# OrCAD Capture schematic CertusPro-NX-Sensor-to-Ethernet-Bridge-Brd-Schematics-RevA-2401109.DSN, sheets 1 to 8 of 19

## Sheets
1 Title Page: title: CP-NX Sensor To Ethernet Bridge Board; rev: 1.0; note: 305-PD-24-0244
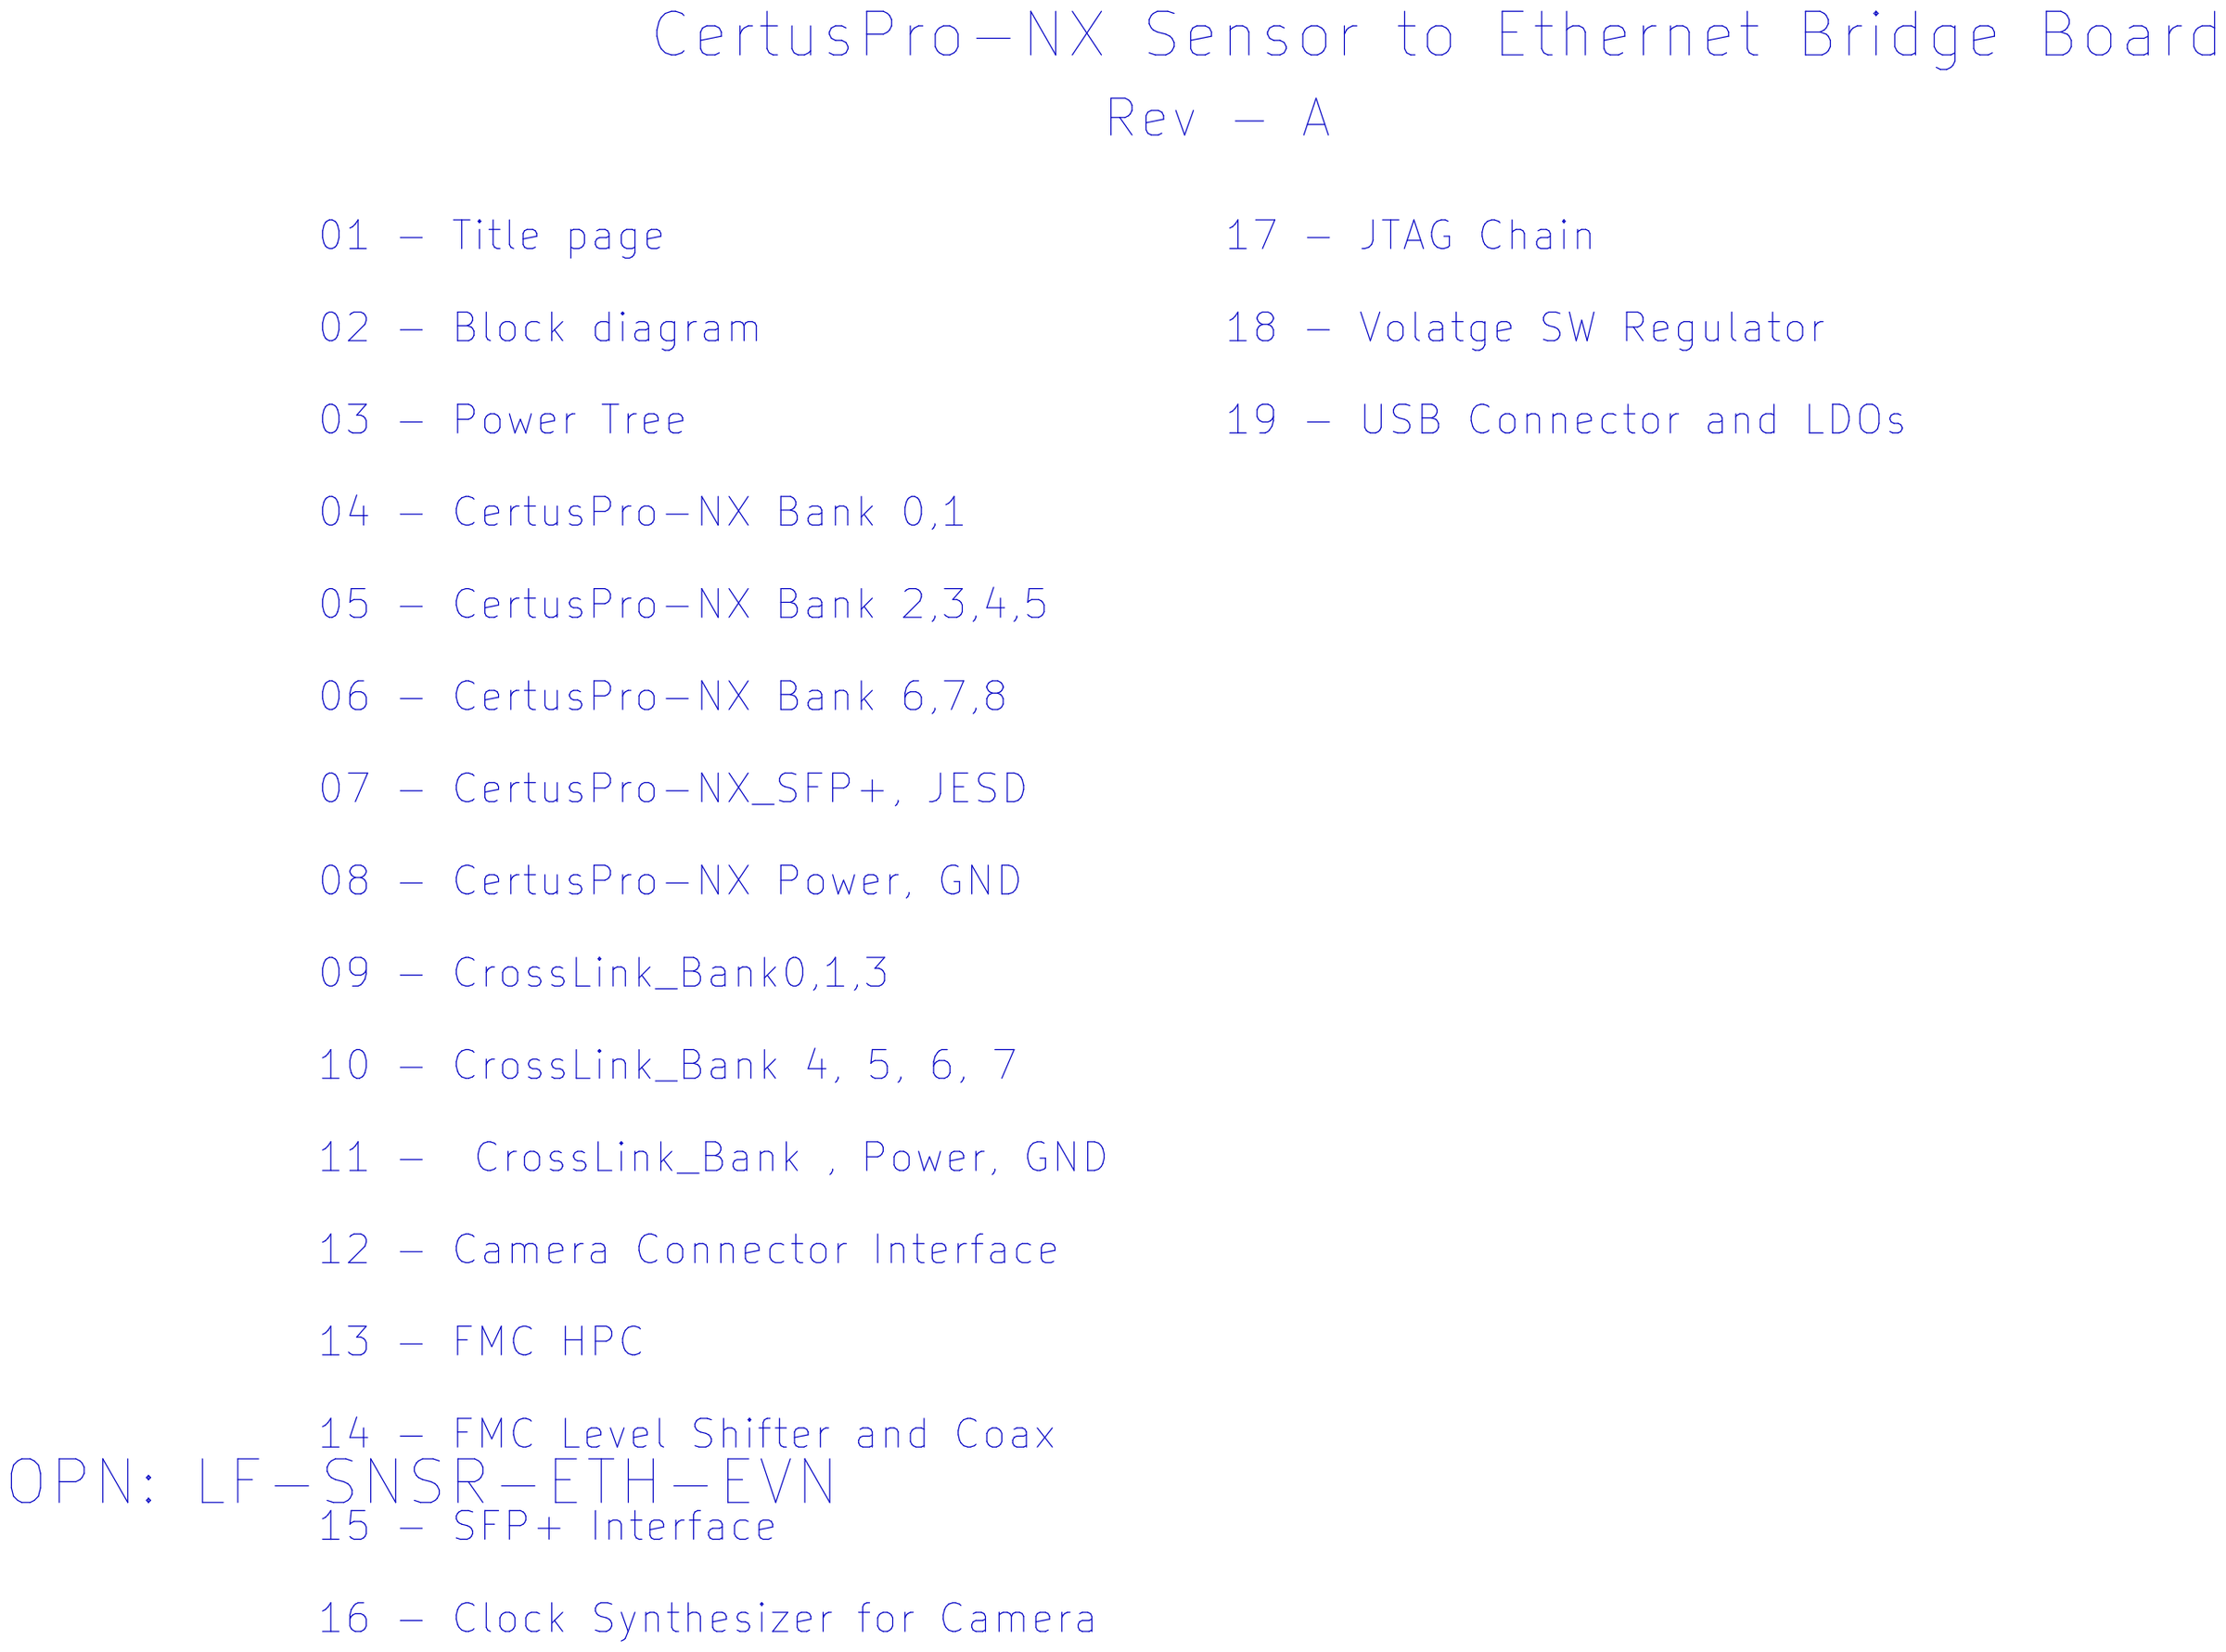
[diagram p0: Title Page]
2 Block Diagram
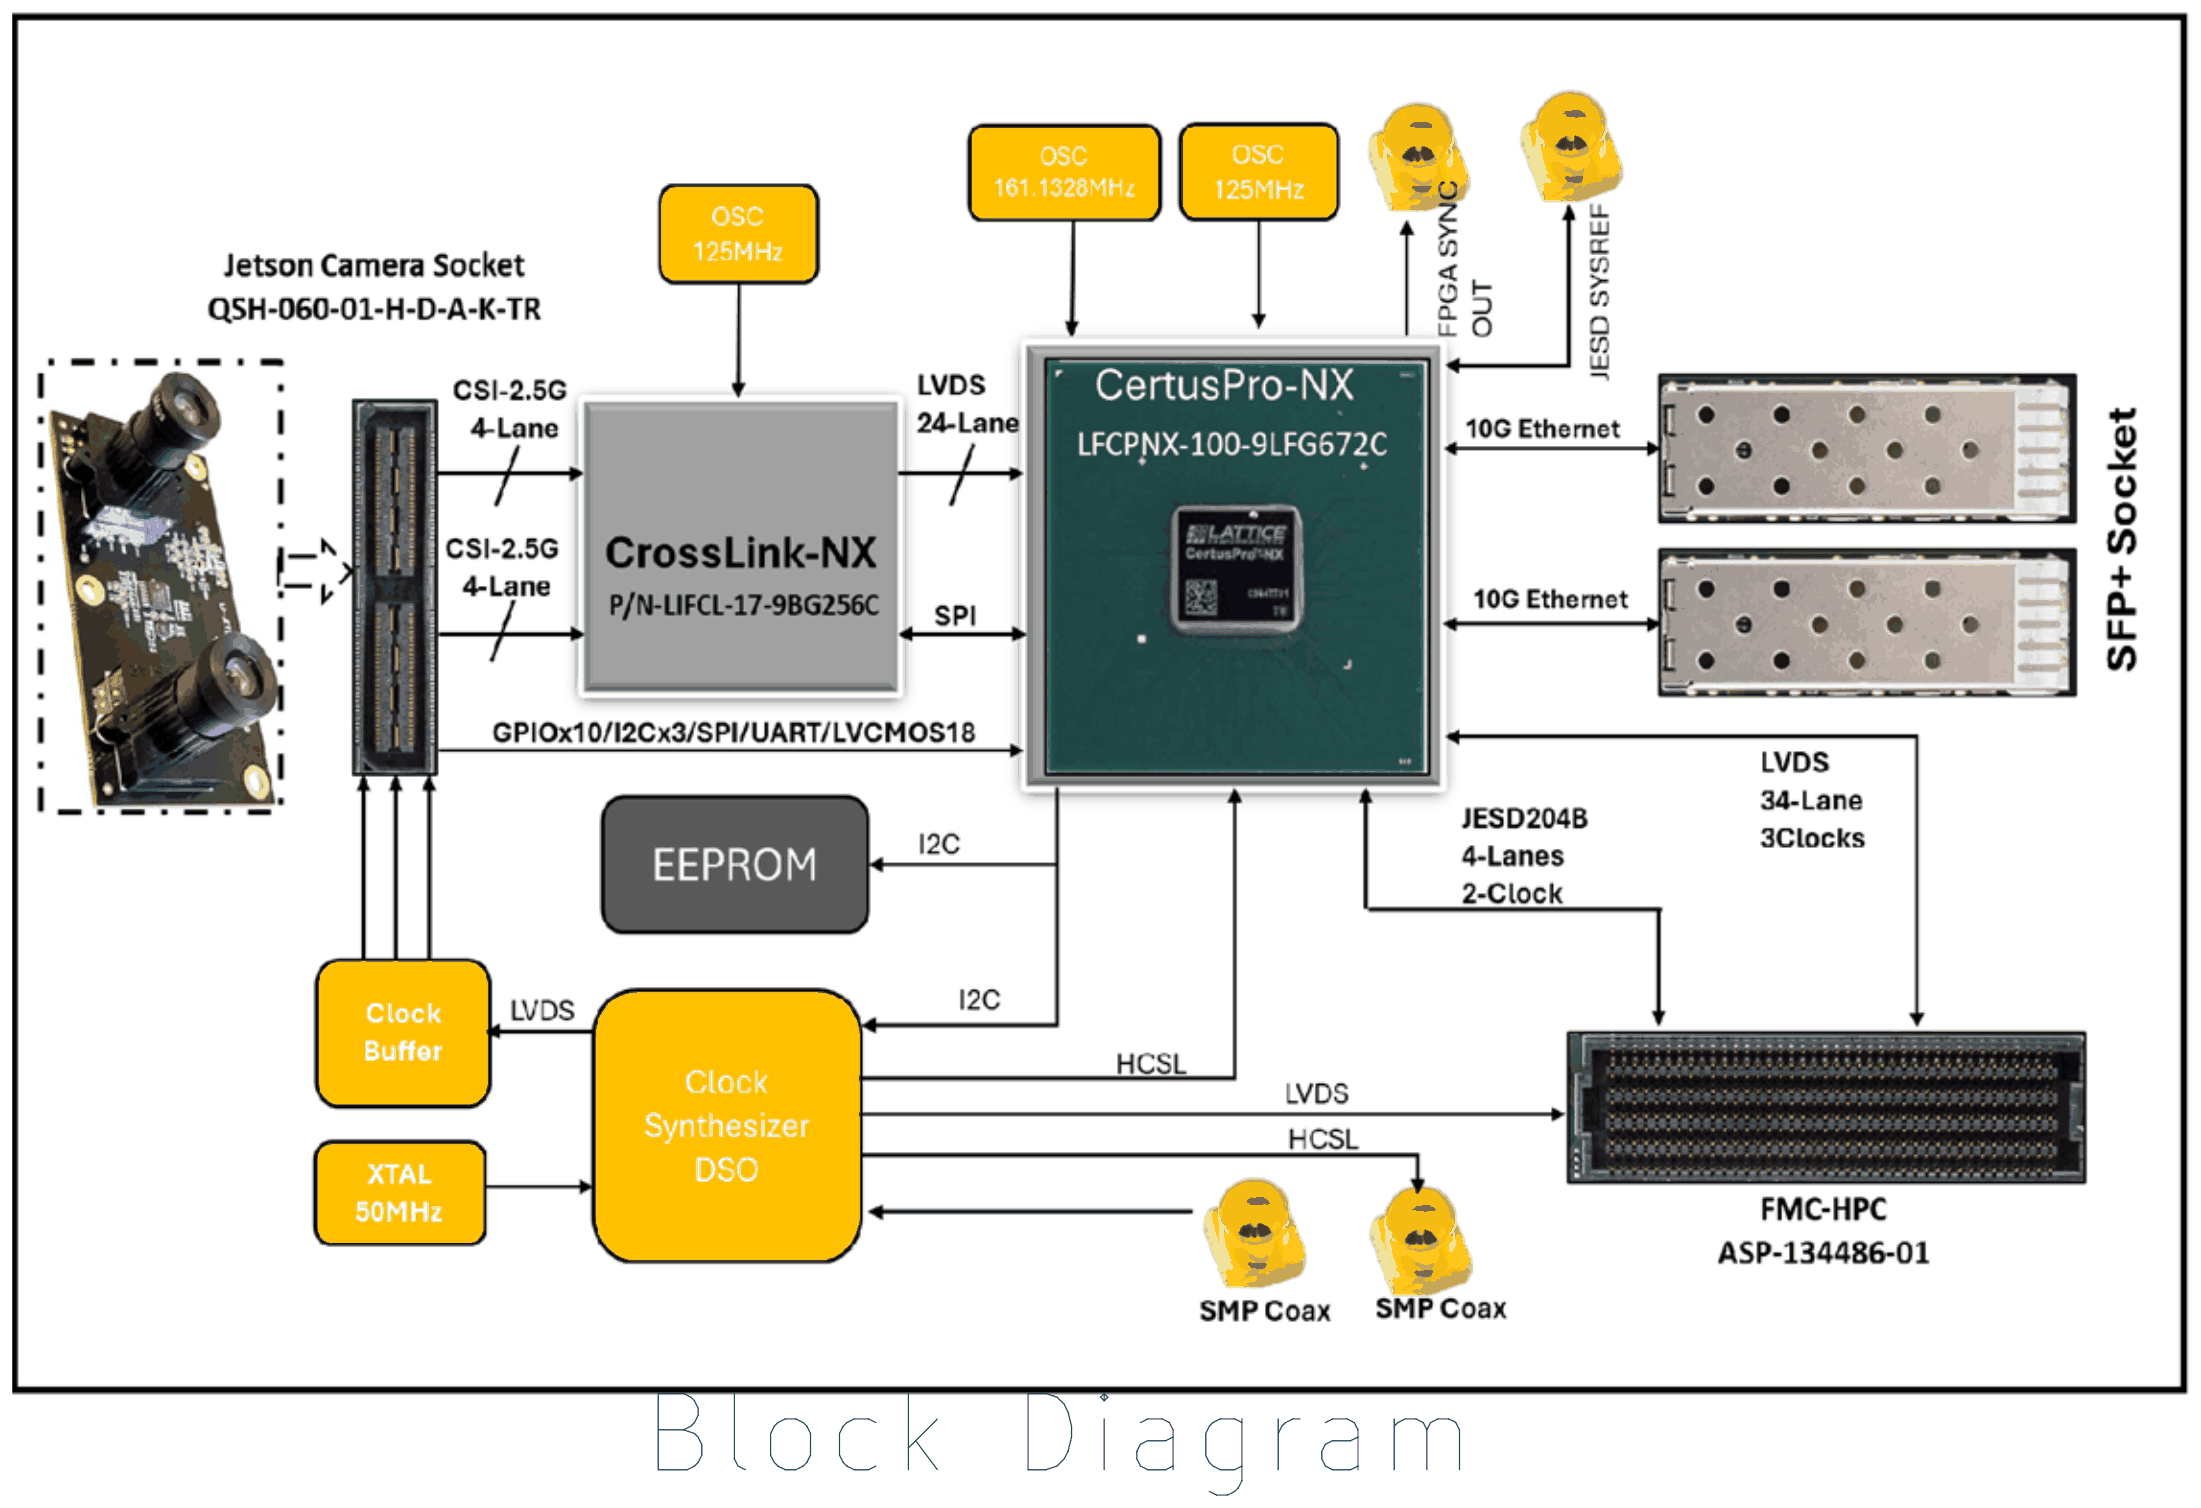
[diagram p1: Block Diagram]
3 Power_Tree
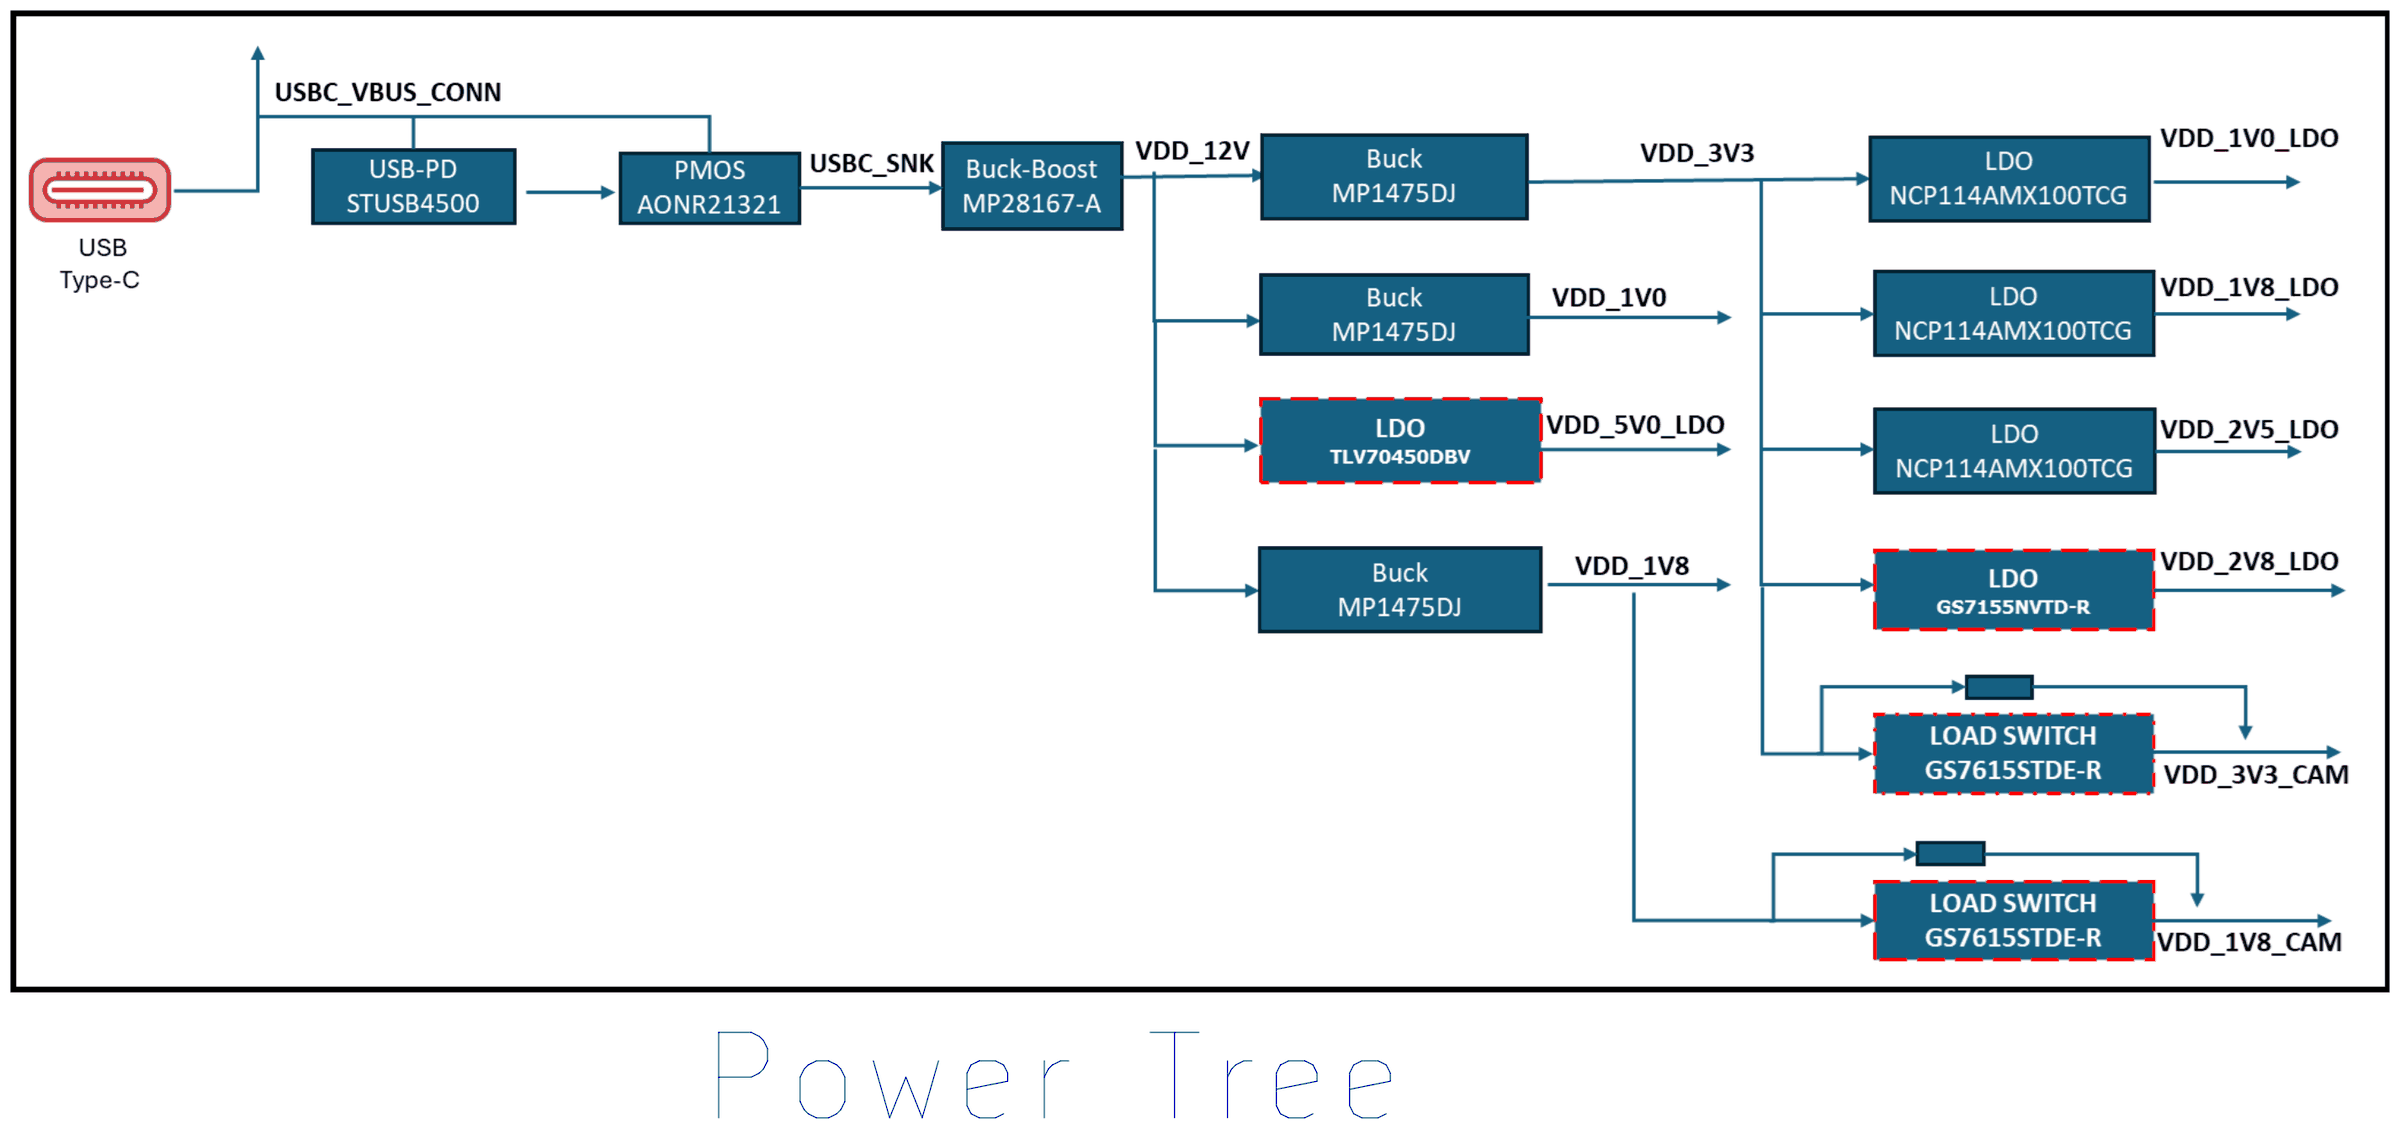
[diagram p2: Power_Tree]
4 CertusPro-NX Bank 0,1: size B
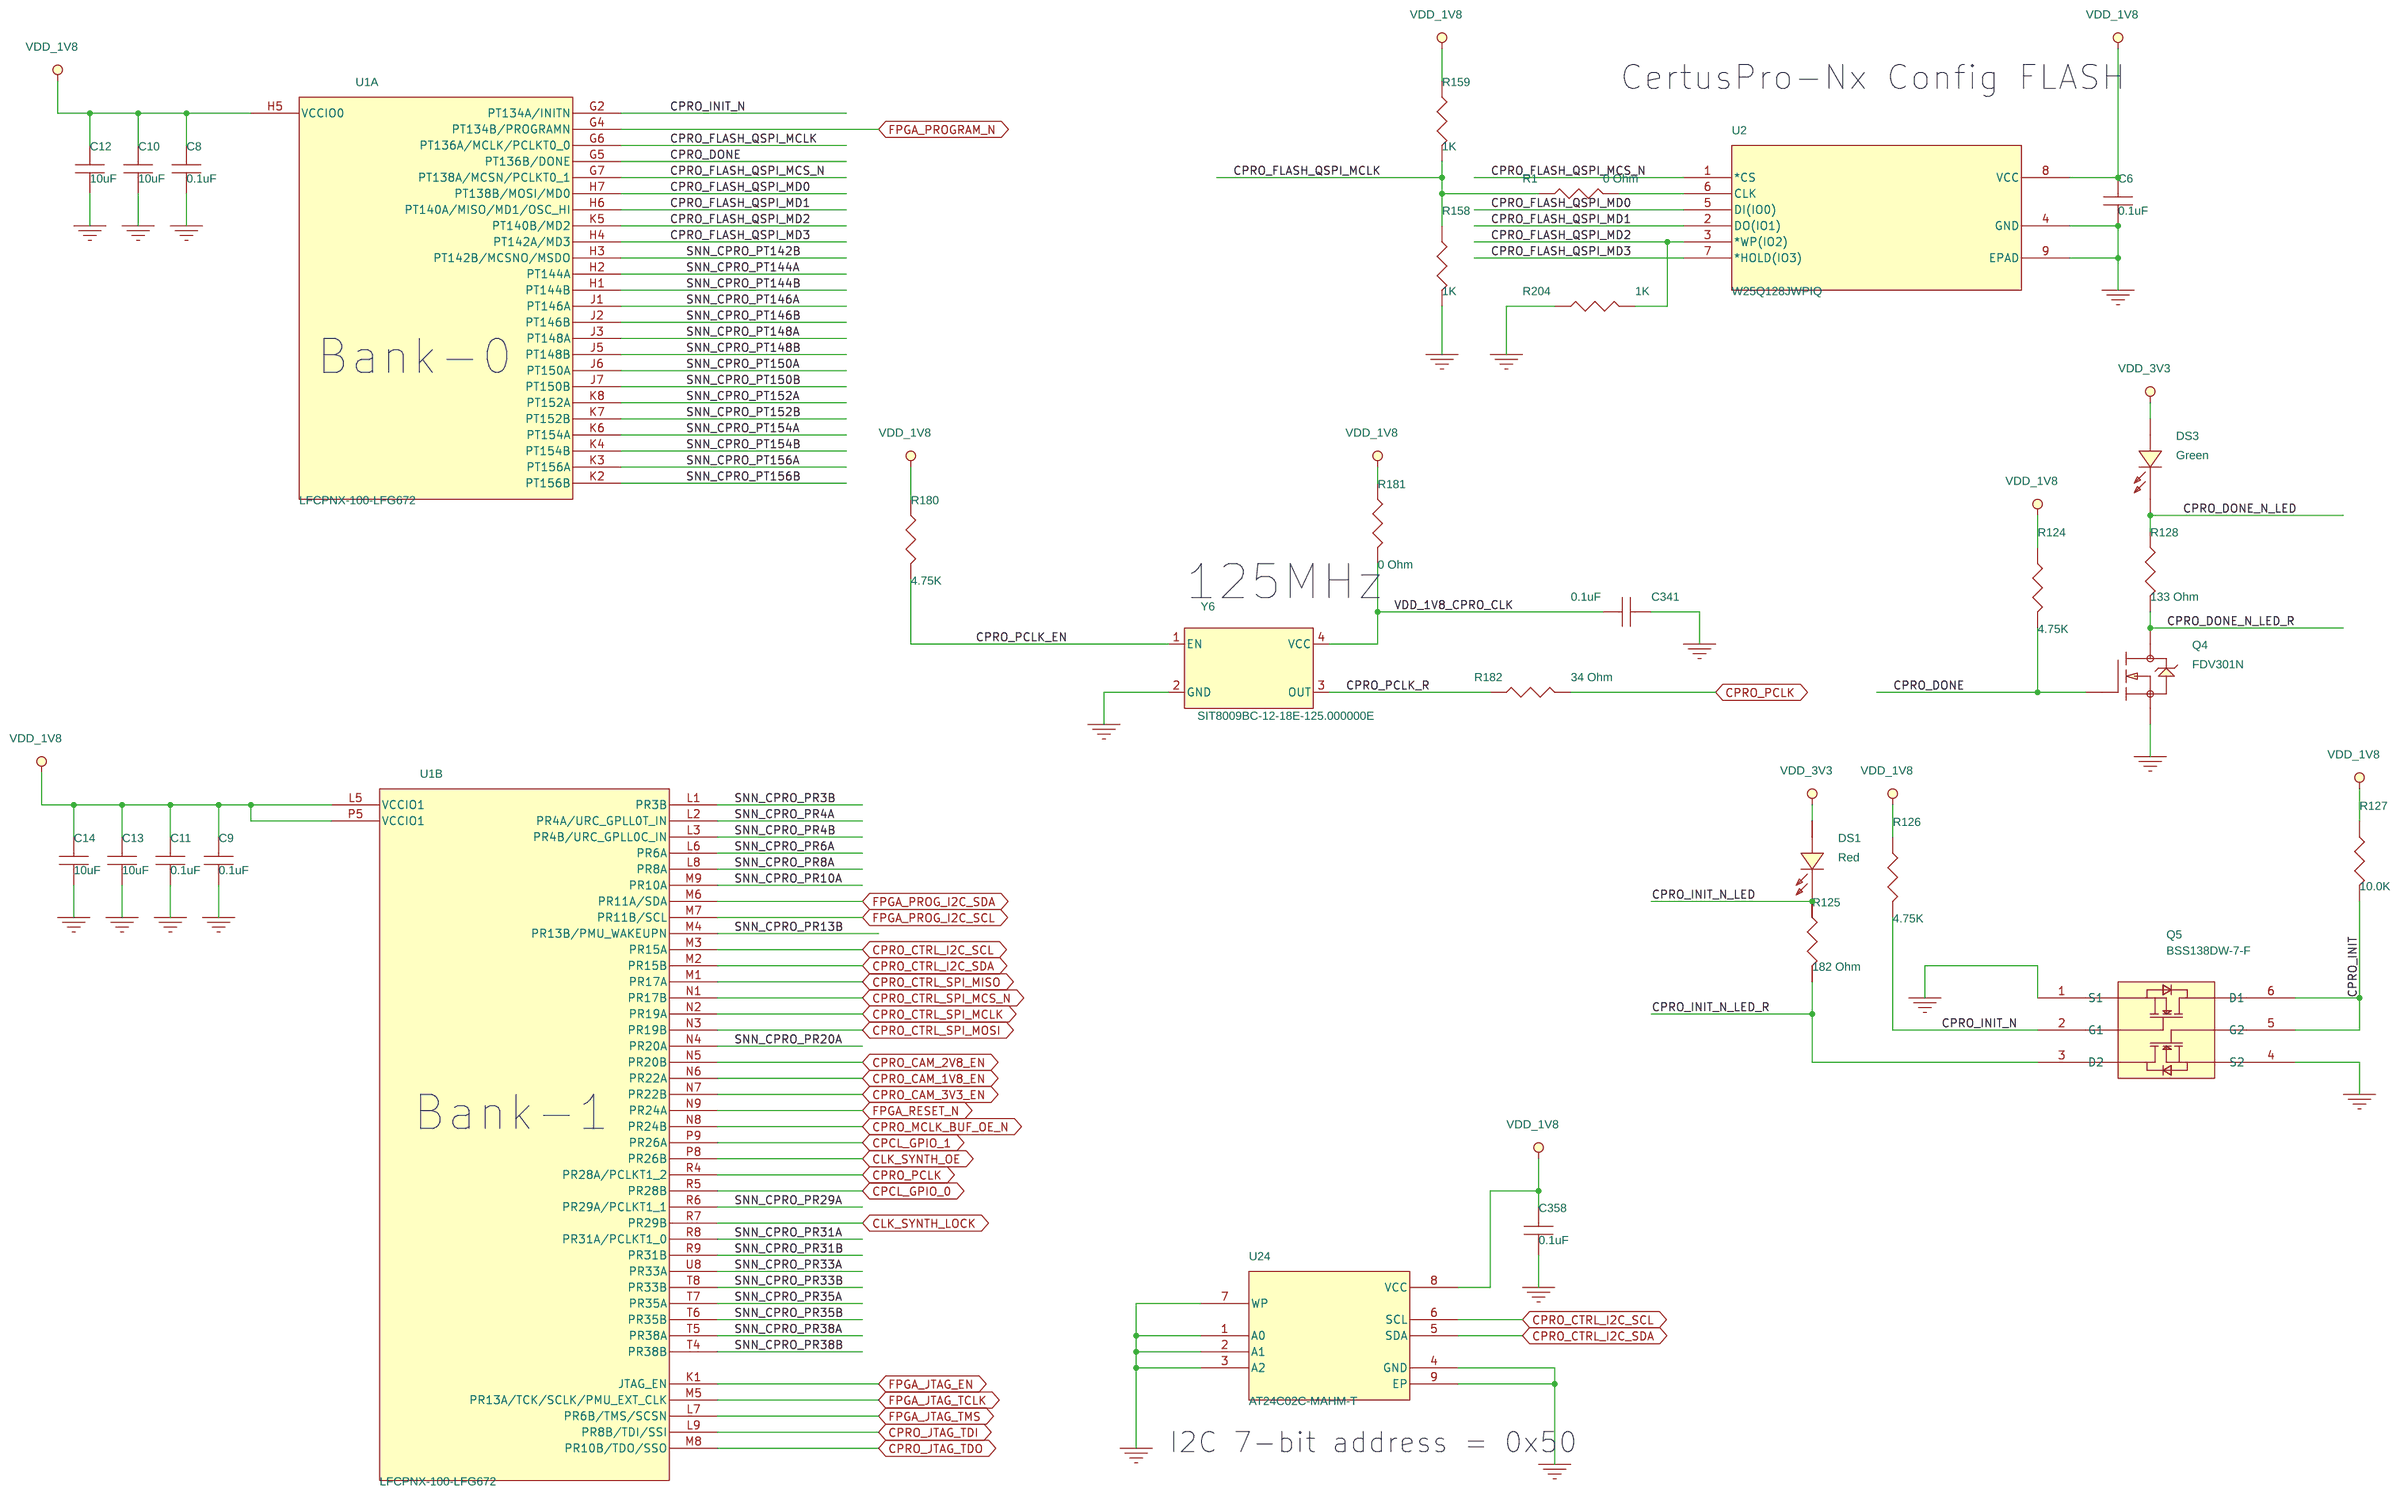
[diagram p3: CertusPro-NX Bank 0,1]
5 CertusPro-NX Bank 2,3,4,5: size B
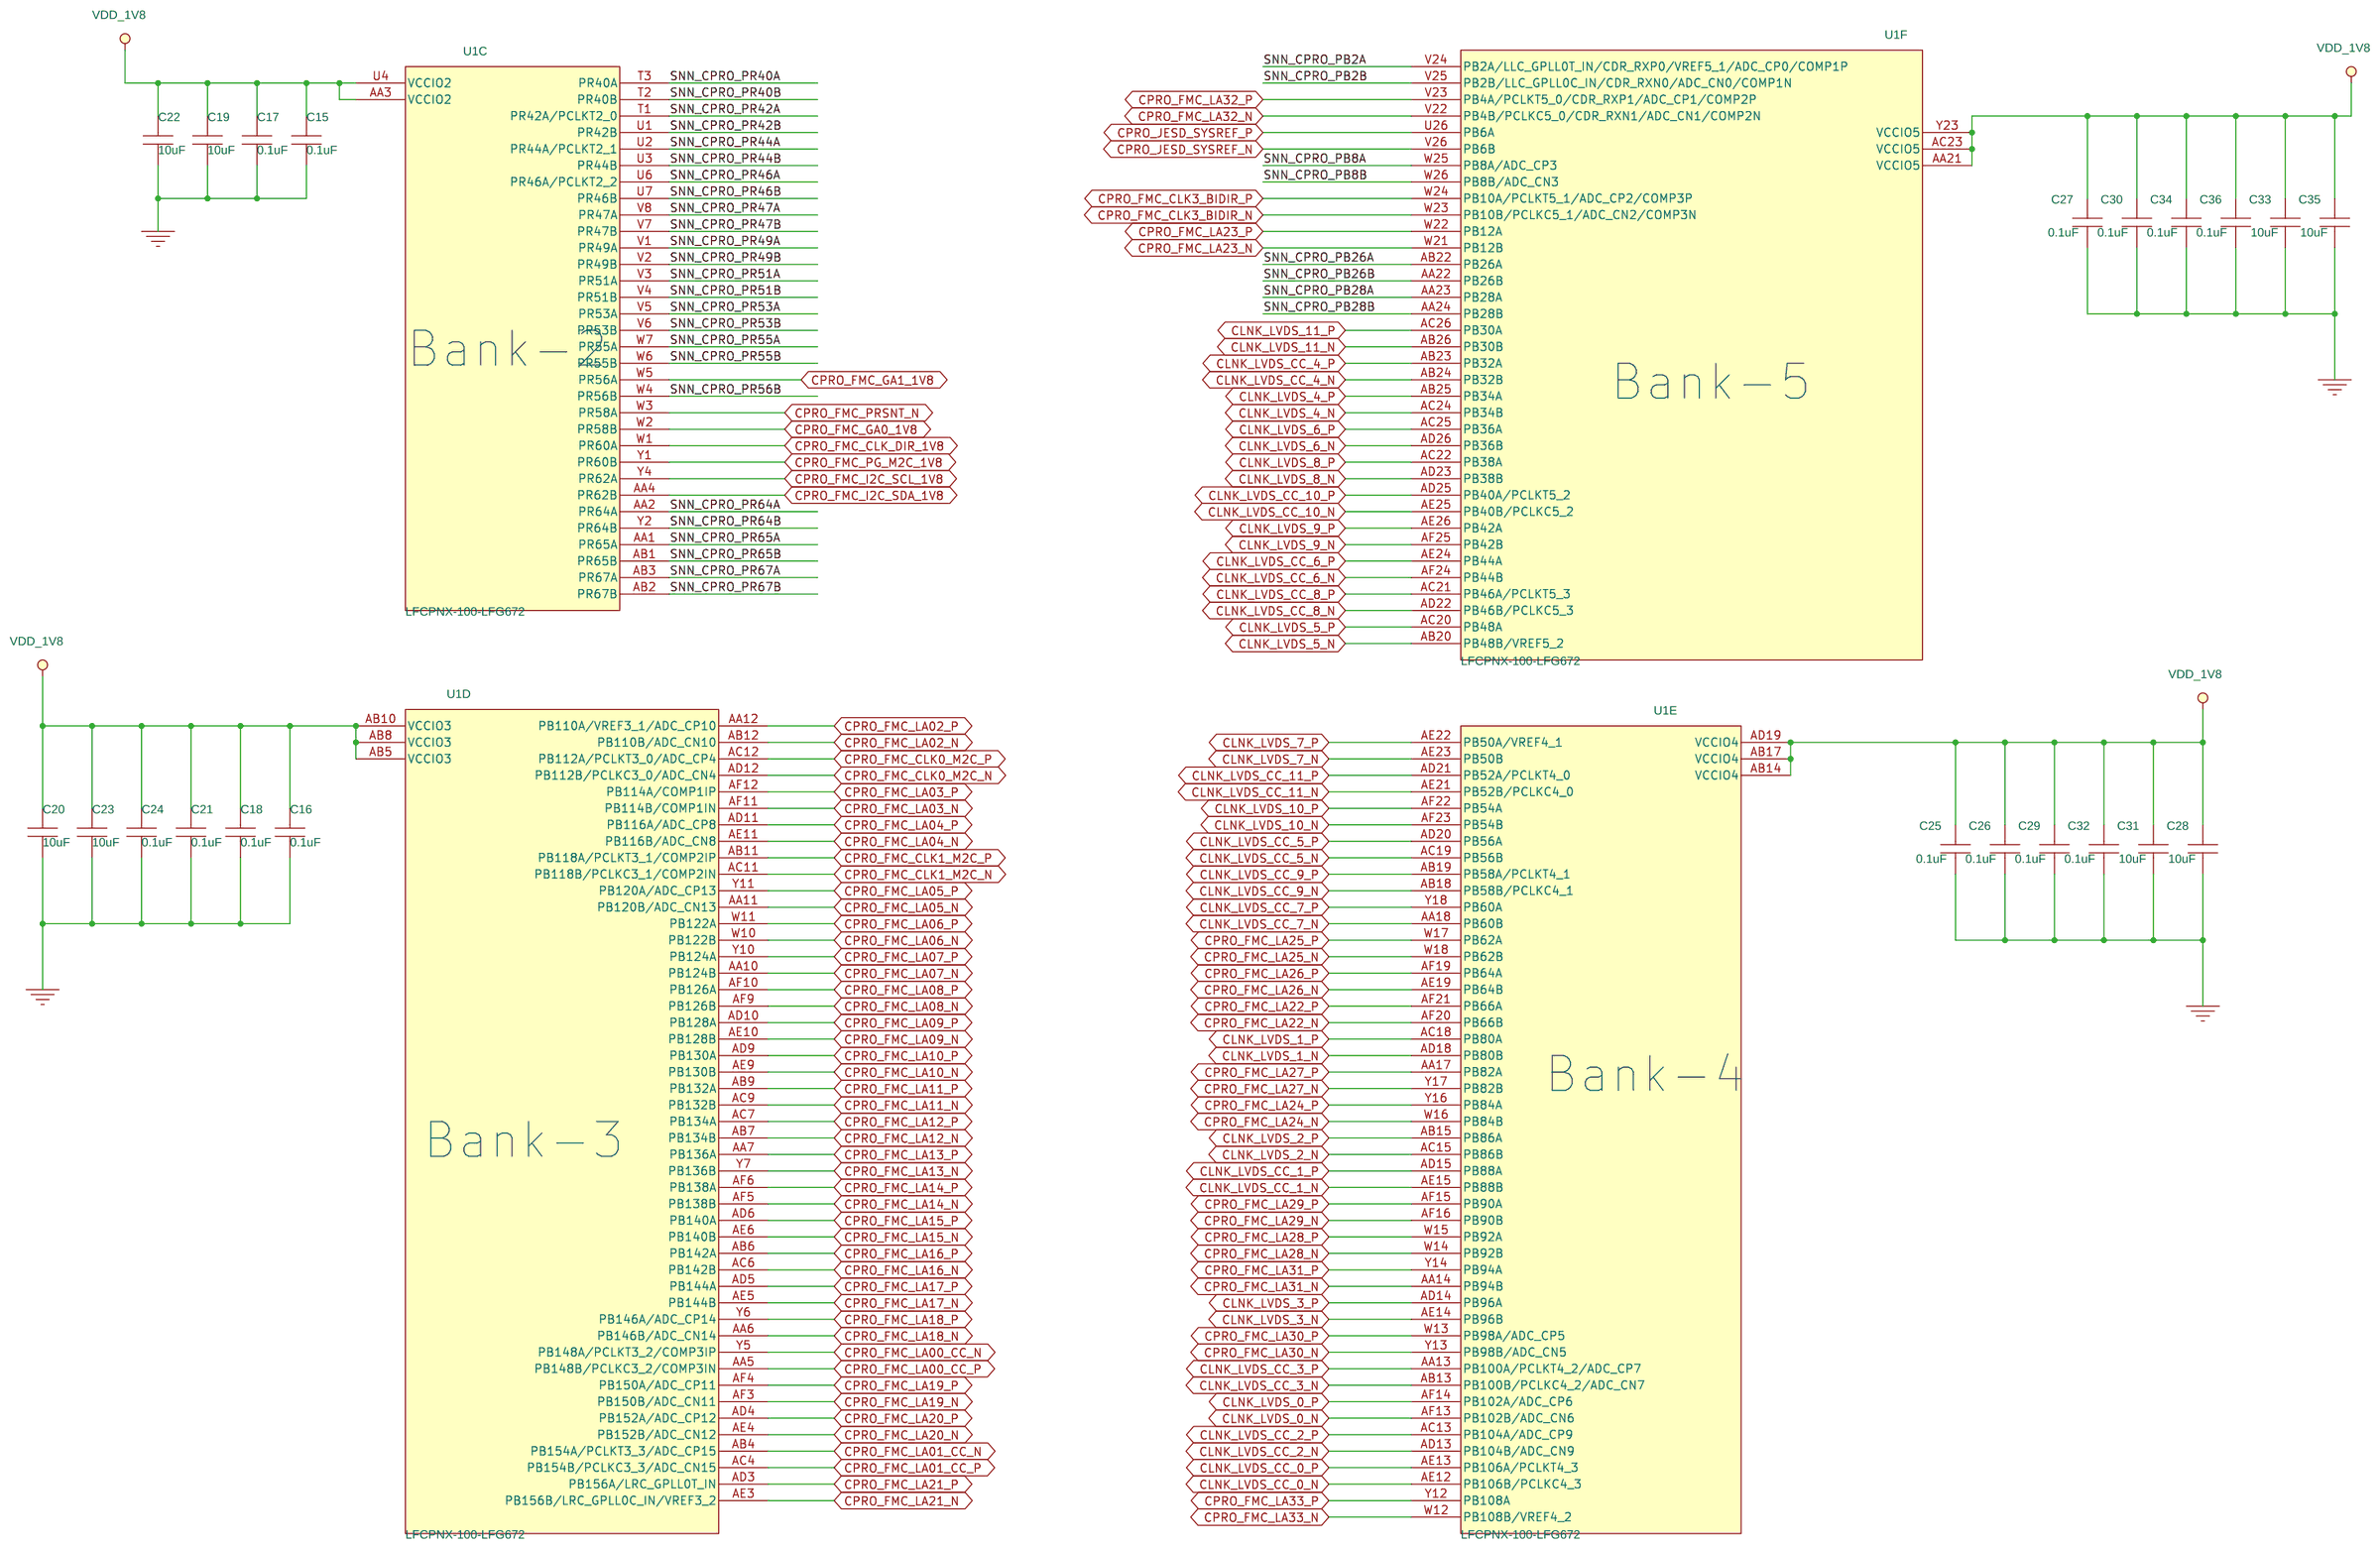
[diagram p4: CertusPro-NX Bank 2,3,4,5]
6 CertusPro-NX Bank 6,7,8: size B
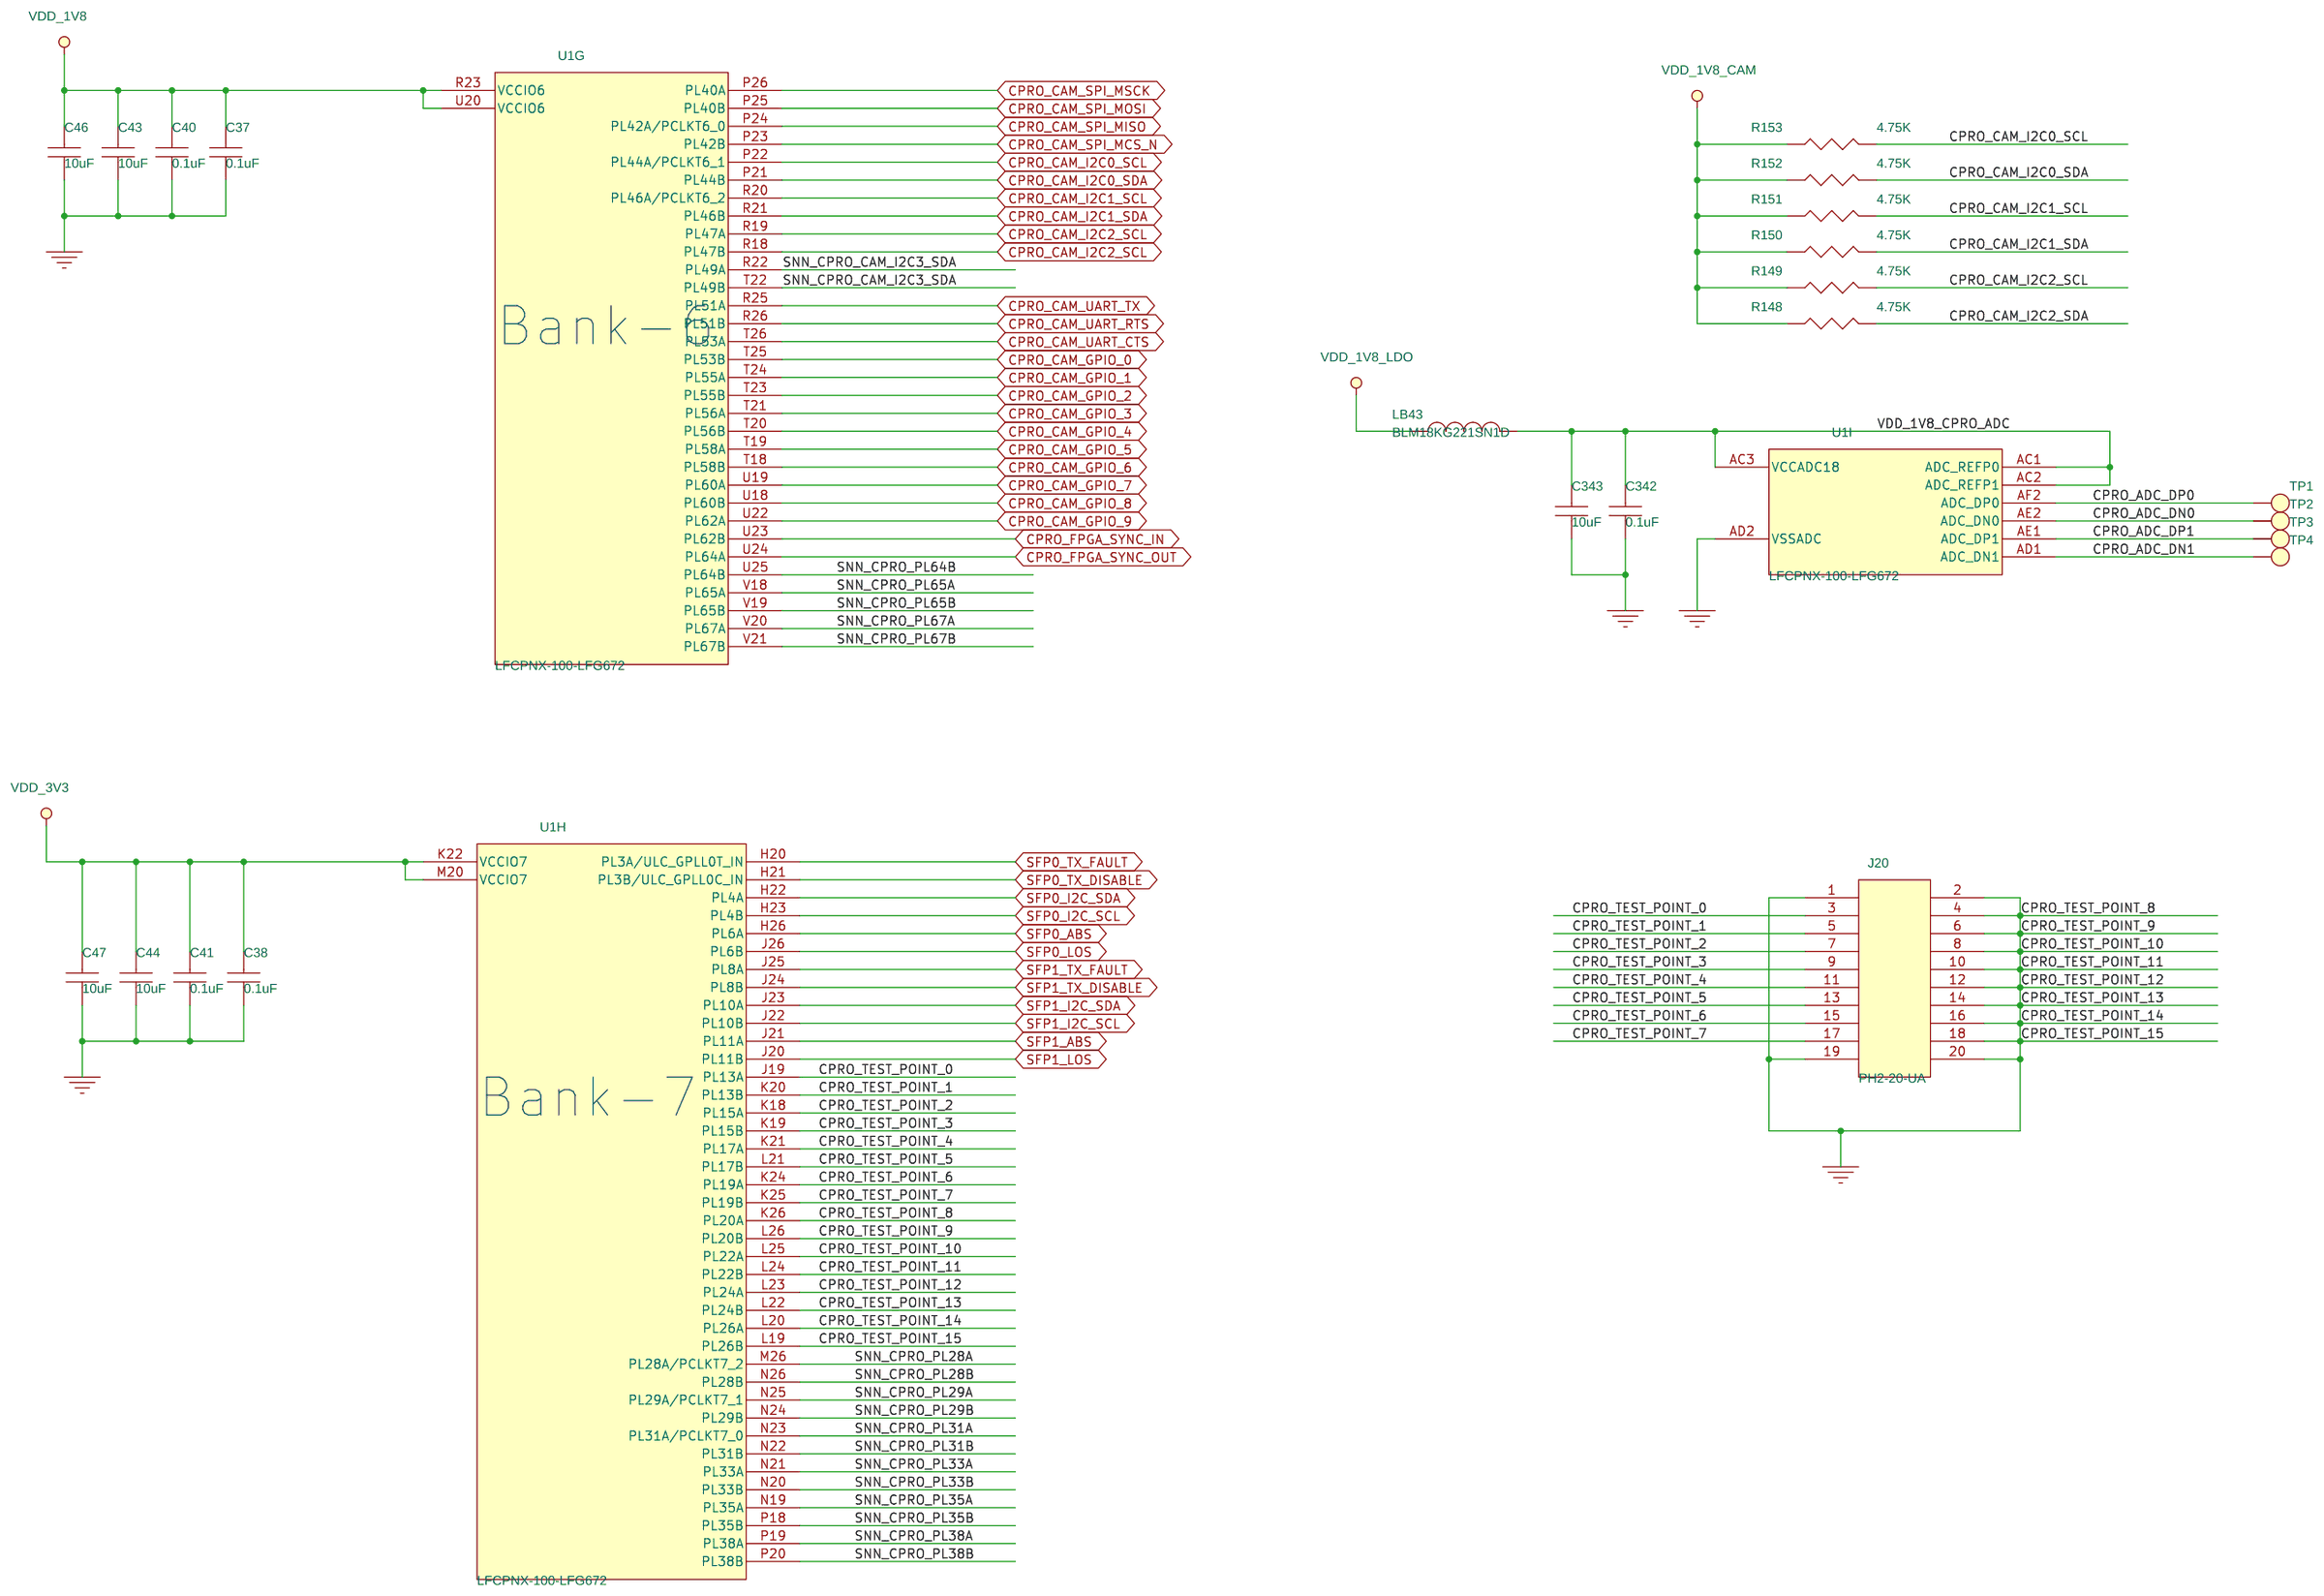
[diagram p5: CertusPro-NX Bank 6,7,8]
7 CertusPro-NX_SFP+,JESD: size B
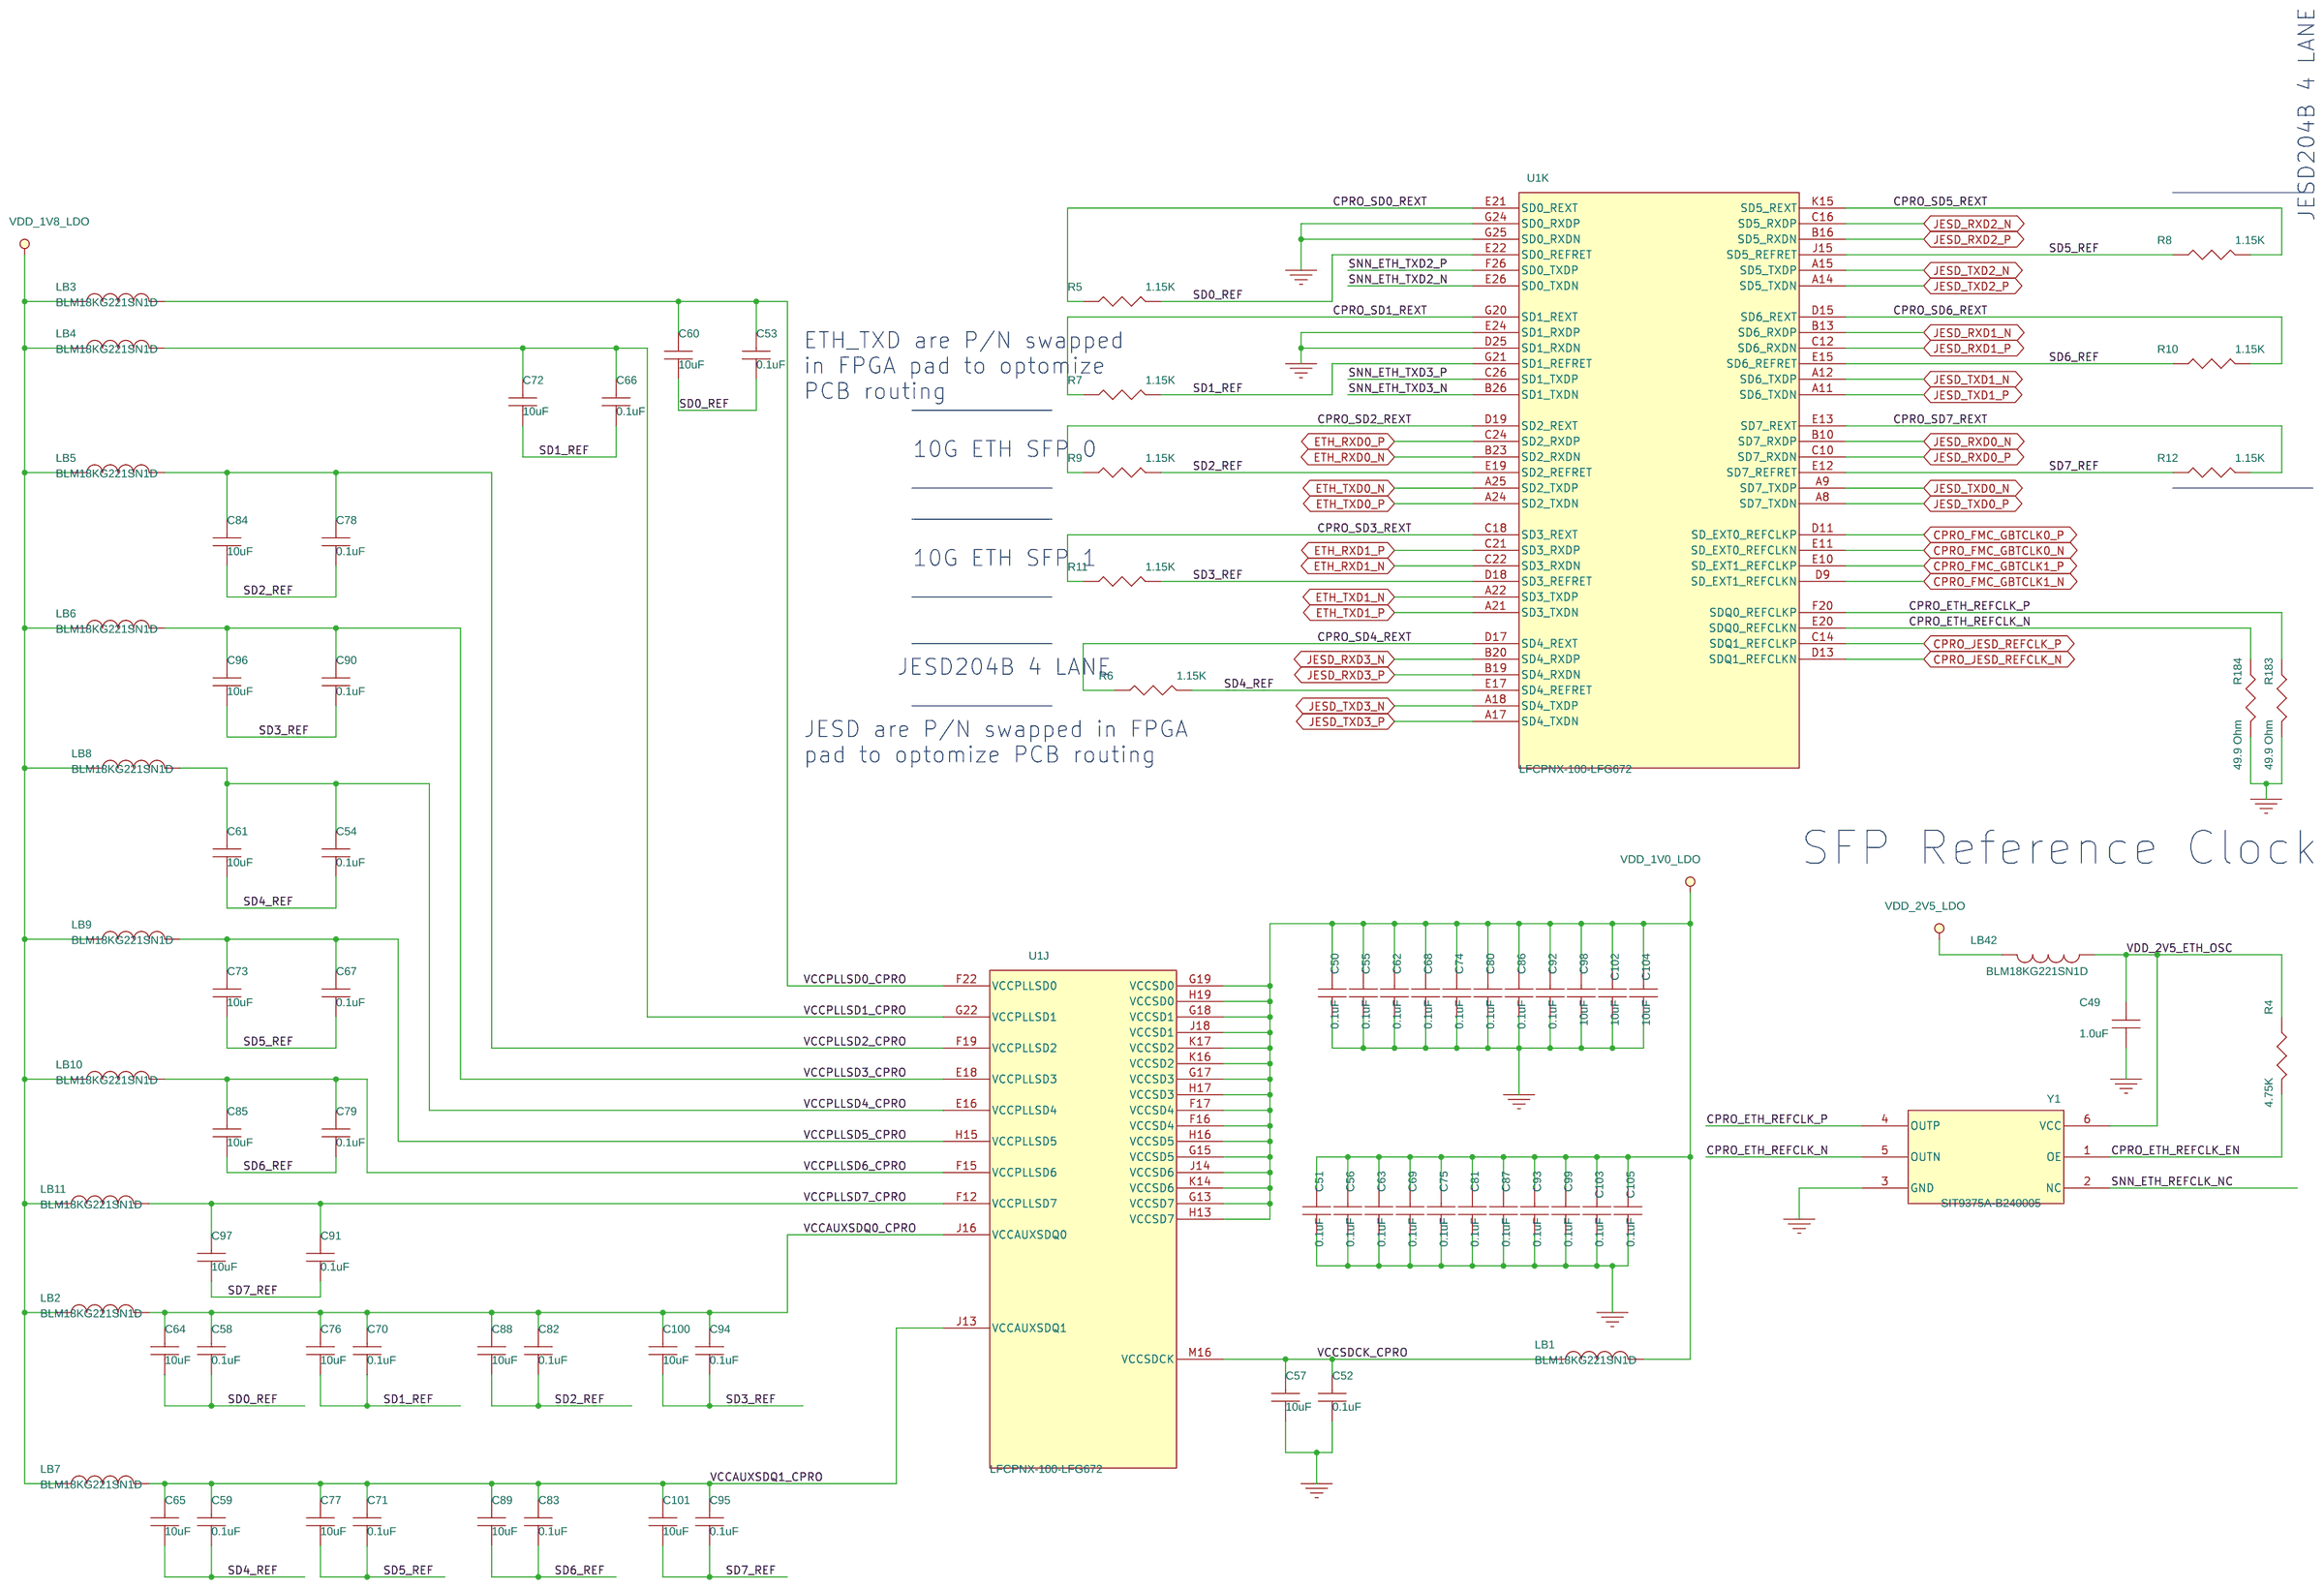
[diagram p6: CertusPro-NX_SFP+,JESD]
8 CertusPro-NX_Power: size B
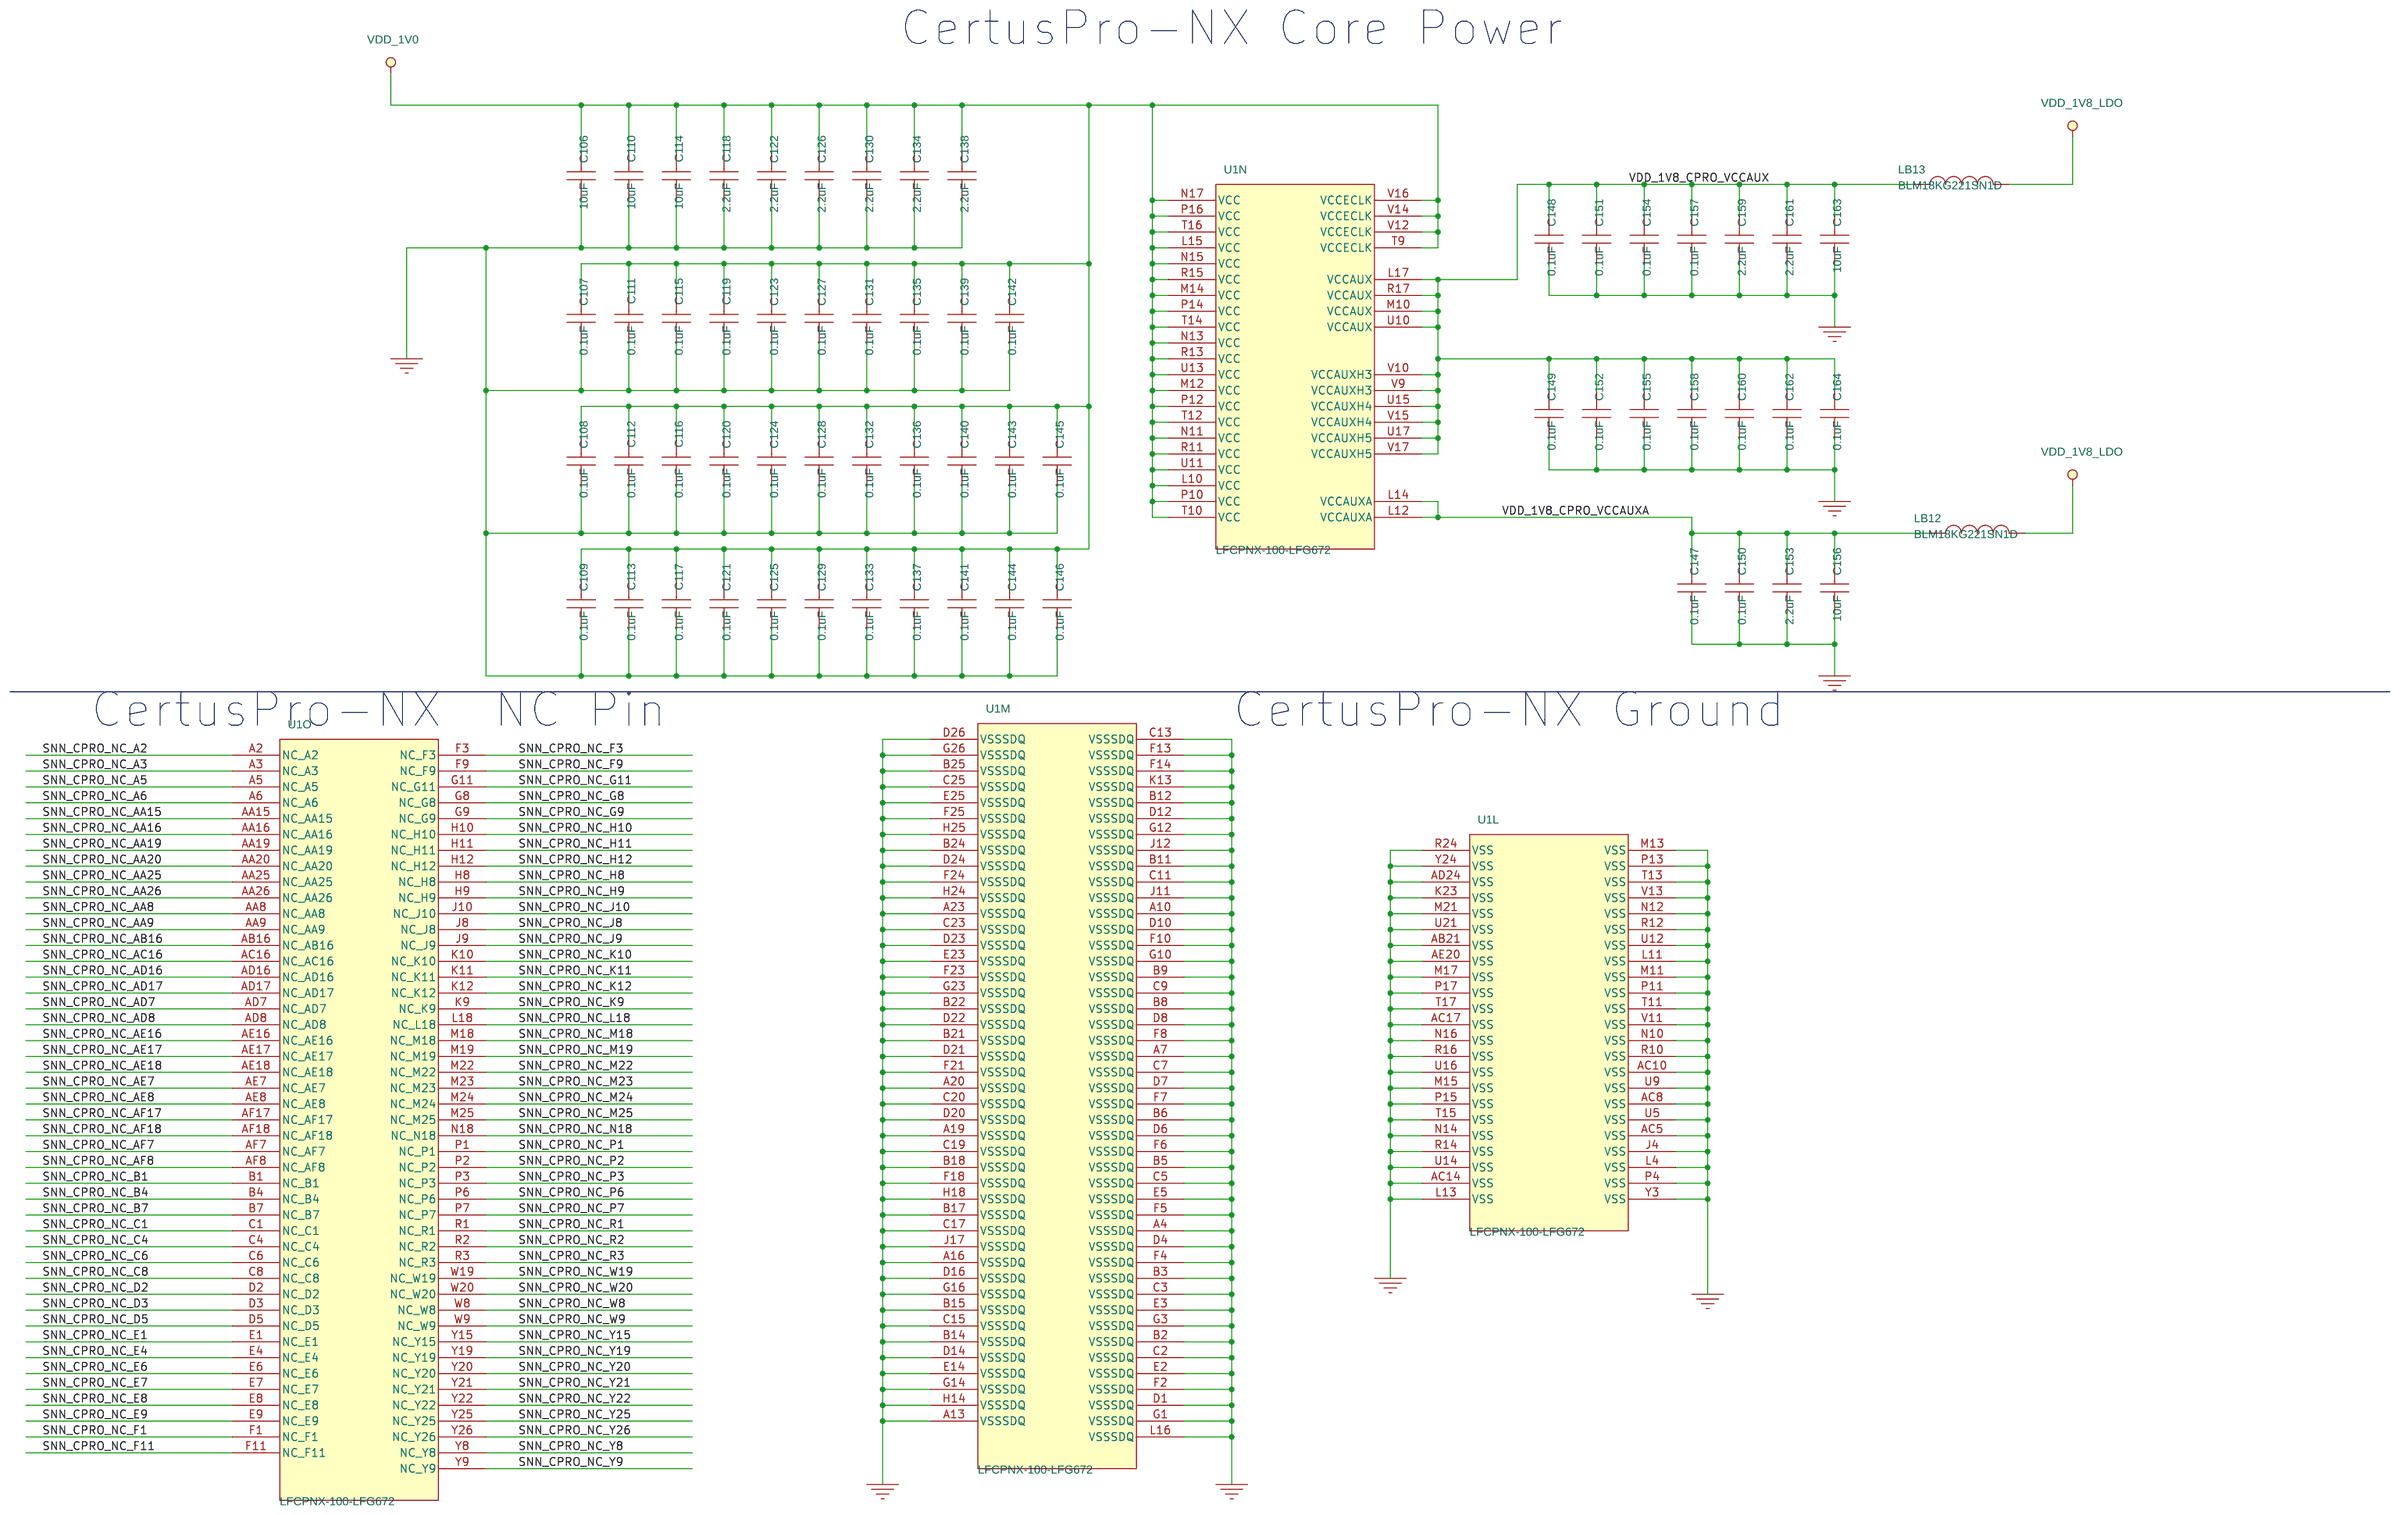
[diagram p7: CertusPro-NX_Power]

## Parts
sheet CertusPro-NX Bank 0,1
C6  0.1uF  [C0402-L]
C8  0.1uF  [C0402-L]
C9  0.1uF  [C0402-L]
C10  10uF  [C0603-L]
C11  0.1uF  [C0402-L]
C12  10uF  [C0603-L]
C13  10uF  [C0603-L]
C14  10uF  [C0603-L]
C341  0.1uF  [C0402-L]
C358  0.1uF  [C0402-L]
DS1  Red  [LED0603]
DS3  Green  [LED0603]
Q4  FDV301N
Q5  BSS138DW-7-F  [SOT363_DIO]
R1  0 Ohm  [R0402-L]
R124  4.75K  [R0402-L]
R125  182 Ohm  [R0402-L]
R126  4.75K  [R0402-L]
R127  10.0K  [R0402-L]
R128  133 Ohm  [R0402-L]
R158  1K  [R0402-L]
R159  1K  [R0402-L]
R180  4.75K  [R0402-L]
R181  0 Ohm  [R0402-L]
R182  34 Ohm  [R0402-L]
R204  1K  [R0402-L]
U2  W25Q128JWPIQ  [WIN_E-8_WIN]
U24  AT24C02C-MAHM-T  [UDFN8_2x3MC_MCH]
Y6  SIT8009BC-12-18E-125.000000E
sheet CertusPro-NX Bank 2,3,4,5
C15  0.1uF  [C0402-L]
C16  0.1uF  [C0402-L]
C17  0.1uF  [C0402-L]
C18  0.1uF  [C0402-L]
C19  10uF  [C0603-L]
C20  10uF  [C0603-L]
C21  0.1uF  [C0402-L]
C22  10uF  [C0603-L]
C23  10uF  [C0603-L]
C24  0.1uF  [C0402-L]
C25  0.1uF  [C0402-L]
C26  0.1uF  [C0402-L]
C27  0.1uF  [C0402-L]
C28  10uF  [C0603-L]
C29  0.1uF  [C0402-L]
C30  0.1uF  [C0402-L]
C31  10uF  [C0603-L]
C32  0.1uF  [C0402-L]
C33  10uF  [C0603-L]
C34  0.1uF  [C0402-L]
C35  10uF  [C0603-L]
C36  0.1uF  [C0402-L]
sheet CertusPro-NX Bank 6,7,8
C37  0.1uF  [C0402-L]
C38  0.1uF  [C0402-L]
C40  0.1uF  [C0402-L]
C41  0.1uF  [C0402-L]
C43  10uF  [C0603-L]
C44  10uF  [C0603-L]
C46  10uF  [C0603-L]
C47  10uF  [C0603-L]
C342  0.1uF  [C0402-L]
C343  10uF  [C0603-L]
J20  PH2-20-UA
LB43  BLM18KG221SN1D
R148  4.75K  [R0402-L]
R149  4.75K  [R0402-L]
R150  4.75K  [R0402-L]
R151  4.75K  [R0402-L]
R152  4.75K  [R0402-L]
R153  4.75K  [R0402-L]
TP1  TP1  [TPd39c60]
TP2  TP1  [TPd39c60]
TP3  TP1  [TPd39c60]
TP4  TP1  [TPd39c60]
sheet CertusPro-NX_Power
C106  10uF  [C0603-L]
C107  0.1uF  [C0402-L]
C108  0.1uF  [C0402-L]
C109  0.1uF  [C0402-L]
C110  10uF  [C0603-L]
C111  0.1uF  [C0402-L]
C112  0.1uF  [C0402-L]
C113  0.1uF  [C0402-L]
C114  10uF  [C0603-L]
C115  0.1uF  [C0402-L]
C116  0.1uF  [C0402-L]
C117  0.1uF  [C0402-L]
C118  2.2uF  [C0402-L]
C119  0.1uF  [C0402-L]
C120  0.1uF  [C0402-L]
C121  0.1uF  [C0402-L]
C122  2.2uF  [C0402-L]
C123  0.1uF  [C0402-L]
C124  0.1uF  [C0402-L]
C125  0.1uF  [C0402-L]
C126  2.2uF  [C0402-L]
C127  0.1uF  [C0402-L]
C128  0.1uF  [C0402-L]
C129  0.1uF  [C0402-L]
C130  2.2uF  [C0402-L]
C131  0.1uF  [C0402-L]
C132  0.1uF  [C0402-L]
C133  0.1uF  [C0402-L]
C134  2.2uF  [C0402-L]
C135  0.1uF  [C0402-L]
C136  0.1uF  [C0402-L]
C137  0.1uF  [C0402-L]
C138  2.2uF  [C0402-L]
C139  0.1uF  [C0402-L]
C140  0.1uF  [C0402-L]
C141  0.1uF  [C0402-L]
C142  0.1uF  [C0402-L]
C143  0.1uF  [C0402-L]
C144  0.1uF  [C0402-L]
C145  0.1uF  [C0402-L]
C146  0.1uF  [C0402-L]
C147  0.1uF  [C0402-L]
C148  0.1uF  [C0402-L]
C149  0.1uF  [C0402-L]
C150  0.1uF  [C0402-L]
C151  0.1uF  [C0402-L]
C152  0.1uF  [C0402-L]
C153  2.2uF  [C0402-L]
C154  0.1uF  [C0402-L]
C155  0.1uF  [C0402-L]
C156  10uF  [C0603-L]
C157  0.1uF  [C0402-L]
C158  0.1uF  [C0402-L]
C159  2.2uF  [C0402-L]
C160  0.1uF  [C0402-L]
C161  2.2uF  [C0402-L]
C162  0.1uF  [C0402-L]
C163  10uF  [C0603-L]
C164  0.1uF  [C0402-L]
LB12  BLM18KG221SN1D
LB13  BLM18KG221SN1D
U1  LFCPNX-100-LFG672  (sections A,B,C,D,E,F,G,H,I,J,K,L,M,N,O)
sheet CertusPro-NX_SFP+,JESD
C49  1.0uF  [C0402-L]
C50  0.1uF  [C0402-L]
C51  0.1uF  [C0402-L]
C52  0.1uF  [C0402-L]
C53  0.1uF  [C0402-L]
C54  0.1uF  [C0402-L]
C55  0.1uF  [C0402-L]
C56  0.1uF  [C0402-L]
C57  10uF  [C0603-L]
C58  0.1uF  [C0402-L]
C59  0.1uF  [C0402-L]
C60  10uF  [C0603-L]
C61  10uF  [C0603-L]
C62  0.1uF  [C0402-L]
C63  0.1uF  [C0402-L]
C64  10uF  [C0603-L]
C65  10uF  [C0603-L]
C66  0.1uF  [C0402-L]
C67  0.1uF  [C0402-L]
C68  0.1uF  [C0402-L]
C69  0.1uF  [C0402-L]
C70  0.1uF  [C0402-L]
C71  0.1uF  [C0402-L]
C72  10uF  [C0603-L]
C73  10uF  [C0603-L]
C74  0.1uF  [C0402-L]
C75  0.1uF  [C0402-L]
C76  10uF  [C0603-L]
C77  10uF  [C0603-L]
C78  0.1uF  [C0402-L]
C79  0.1uF  [C0402-L]
C80  0.1uF  [C0402-L]
C81  0.1uF  [C0402-L]
C82  0.1uF  [C0402-L]
C83  0.1uF  [C0402-L]
C84  10uF  [C0603-L]
C85  10uF  [C0603-L]
C86  0.1uF  [C0402-L]
C87  0.1uF  [C0402-L]
C88  10uF  [C0603-L]
C89  10uF  [C0603-L]
C90  0.1uF  [C0402-L]
C91  0.1uF  [C0402-L]
C92  0.1uF  [C0402-L]
C93  0.1uF  [C0402-L]
C94  0.1uF  [C0402-L]
C95  0.1uF  [C0402-L]
C96  10uF  [C0603-L]
C97  10uF  [C0603-L]
C98  10uF  [C0603-L]
C99  0.1uF  [C0402-L]
C100  10uF  [C0603-L]
C101  10uF  [C0603-L]
C102  10uF  [C0603-L]
C103  0.1uF  [C0402-L]
C104  10uF  [C0603-L]
C105  0.1uF  [C0402-L]
LB1  BLM18KG221SN1D
LB2  BLM18KG221SN1D
LB3  BLM18KG221SN1D
LB4  BLM18KG221SN1D
LB5  BLM18KG221SN1D
LB6  BLM18KG221SN1D
LB7  BLM18KG221SN1D
LB8  BLM18KG221SN1D
LB9  BLM18KG221SN1D
LB10  BLM18KG221SN1D
LB11  BLM18KG221SN1D
LB42  BLM18KG221SN1D
R4  4.75K  [R0402-L]
R5  1.15K  [R0402-L]
R6  1.15K  [R0402-L]
R7  1.15K  [R0402-L]
R8  1.15K  [R0402-L]
R9  1.15K  [R0402-L]
R10  1.15K  [R0402-L]
R11  1.15K  [R0402-L]
R12  1.15K  [R0402-L]
R183  49.9 Ohm  [R0402-L]
R184  49.9 Ohm  [R0402-L]
Y1  SIT9375A-B240005

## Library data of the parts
C6 C8 C9 C11 C15-C18 C21 C24-C27 C29 C30 C32 C34 C36-C38 C40 C41 C50-C56 C58 C59 C62 C63 C66-C71 C74 C75 C78-C83 C86 C87 C90-C95 C99 C103 C105 C341 C342 C358 = CAP_NP: 0.1 µF ±10% 50V Ceramic Capacitor X7R 0402 (1005 Metric); Manufacturer: Murata; Manufacturer Part Number: GRM155R71H104KE14J; Part Number: GRM155R71H104KE14J; Part type: Ceramic; Tolerance: 10%; Voltage: 50V; Datasheet: https://search.murata.co.jp/Ceramy/image/img/A01X/G101/ENG/GRM155R71H104KE14-01.pdf
C10 C12-C14 C19 C20 C22 C23 C28 C31 C33 C35 C43 C44 C46 C47 C57 C60 C61 C64 C65 C72 C73 C76 C77 C84 C85 C88 C89 C96-C98 C100-C102 C104 C343 = CAP_NP: CAP NCS X5R 0603 10uF +/-20% 6.3V; Manufacturer: AVX Corporation; Manufacturer Part Number: 06036D106MAT2A; Part Number: 06036D106MAT2A; Part type: Ceramic; Tolerance: 20%; Voltage: 6.3V; Datasheet: https://datasheets.kyocera-avx.com/cx5r-KGM.pdf
DS1 = LED: LED 0603 SML-D12U1W 2.2V 20mA Red 620nm 63mcd; Current: 20mA; Manufacturer: ROHM Co., Ltd.; Manufacturer Part Number: SML-D12U1W; Part Number: SML-D12U1W; Voltage: 2.2V
DS3 = LED: LED 0603 KPT-1608-RY231 2.5V 30mA Green 5V VER; Current: 30mA; Manufacturer: Kingbright Electronic Co., Ltd.; Manufacturer Part Number: KPT-1608-RY231; Part Number: KPT-1608-RY231; Voltage: 2.5V
Q4 = N-MOS: MOSFET N-CH 25V 220MA SOT23; Manufacturer: ON Semiconductor Corporation; Part Type: MOSFET N-CH; Datasheet: https://www.onsemi.com/pdf/datasheet/fdv301n-d.pdf
Q5 = BSS138DW-7: MOSFET 2N-CH 50V 0.2A SOT363; Manufacturer: Diodes Incorporated; Part Type: MOSFET N-CH; Datasheet: https://www.diodes.com/assets/Datasheets/ds30203.pdf
R1 R181 = R: 0 Ohms Jumper Chip Resistor 0402 (1005 Metric) Moisture Resistant Thick Film; Manufacturer: Yageo; Manufacturer Part Number: RC0402FR-070RL; Part Number: RC0402FR-070RL; Part type: Thick Film; Datasheet: https://www.yageo.com/upload/media/product/productsearch/datasheet/rchip/PYu-RC_Group_51_RoHS_L_12.pdf
R4 R124 R126 R148-R153 R180 = R: RES 0402 4.75kohm 1% 62.5mW; Manufacturer: Matsushita Electric Works, Ltd.; Manufacturer Part Number: ERJ2RKF4751X; Part Number: ERJ2RKF4751X; Part type: Thick Film; Power: 62.5mW; Tolerance: 1%
R125 = R: RES 0402 182ohm 1% 62.5mW; Manufacturer: Matsushita Electric Works, Ltd.; Manufacturer Part Number: ERJ2RKF1820X; Part Number: ERJ2RKF1820X; Part type: Thick Film; Power: 62.5mW; Tolerance: 1%
R127 = R: 10 kOhms ±1% 0.063W, 1/16W Chip Resistor 0402 (1005 Metric) Thick Film; Manufacturer: Yageo; Manufacturer Part Number: RC0402FR-0710KP; Part Number: RC0402FR-0710KP; Part type: Thick Film; Power: 1/16W; Tolerance: 1%; Datasheet: https://www.yageo.com/upload/media/product/products/datasheet/rchip/PYu-RC_51_RoHS_P_4.pdf
R128 = R: RES 0402 133ohm 1% 62.5mW; Manufacturer: SAMSUNG ELECTRONICS CO., LTD.; Manufacturer Part Number: RC1005F1330CS; Part Number: RC1005F1330CS; Part type: Thick Film; Power: 62.5mW; Tolerance: 1%
R158 R159 R204 = R: RES 0402 1kohm 1% 62.5mW; Manufacturer: TA-I Technology Co., Ltd.; Manufacturer Part Number: RM04FTN1001; Part Number: RM04FTN1001; Part type: Thick Film; Power: 62.5mW; Tolerance: 1%
R182 = R: RES 0402 34ohm 1% 62.5mW; Manufacturer: Yageo Corporation; Manufacturer Part Number: RC0402FR-0734RL; Part Number: RC0402FR-0734RL; Part type: Thick Film; Power: 50rporationFR-; Tolerance: 1%
U2 = W25Q128JW: FLASH - NOR Memory IC 128Mbit SPI - Quad I/O 133 MHz 8-WSON (6x5); Manufacturer: Winbond Electronics Corporation; Part Type: FLASH; Datasheet: https://www.winbond.com/resource-files/W25Q128JW_RevG_07292021%20Plus.pdf
U24 = AT24C02C: EEPROM Memory IC 2Kbit I2C 1 MHz 550 ns 8-UDFN (2x3); Manufacturer: Microchip Technology, Inc.; Part Type: EEPROM; Datasheet: https://ww1.microchip.com/downloads/en/DeviceDoc/AT24C01C-AT24C02C-I2C-Compatible-Two-Wire-Serial-EEPROM-1Kbit-2Kbit-20006111A.pdf
Y6 = SiT8009B_0: MEMS OSC XO 125.0000MHZ H/LVCMOS; Manufacturer: SiTime Corporation; Part Type: Oscillator; Datasheet: https://www.sitime.com/datasheet/SiT8009
J20 = PH2-20-UA: Connector Header Through Hole 20 position 0.100" (2.54mm); Manufacturer: Adam Tech; Part Type: Connector; Datasheet: https://app.adam-tech.com/products/download/data_sheet/202065/ph2-xx-ua-data-sheet.pdf
LB1-LB13 LB42 LB43 = LB_Inductor: 220 Ohms @ 100 MHz 1 Power Line Ferrite Bead 0603 (1608 Metric) 2.2A 50mOhm; Current: 2.2A; DCR: 50mohm; Manufacturer: Murata Electronics
TP1-TP4 = TP1: Test Point 0.39"; Manufacturer: NA; Part Type: Test Point; Datasheet: NA
C106 C110 C114 C156 C163 = CAP_NP: CAP CER 10UF 6.3V X5R 0603; Manufacturer: KEMET; Manufacturer Part Number: C0603C106M9PAC7867; Part Number: C0603C106M9PAC7867; Part type: Ceramic; Tolerance: 20%; Voltage: 6.3V
C107-C109 C111-C113 C115-C117 C119-C121 C123-C125 C127-C129 C131-C133 C135-C137 C139-C152 C154 C155 C157 C158 C160 C162 C164 = CAP_NP: CAP CER 0.1UF 16V X7R 0402; Manufacturer: KEMET; Manufacturer Part Number: C0402C104K4RACTU; Part Number: C0402C104K4RACTU; Part type: Ceramic; Tolerance: 10%; Voltage: 16V
C118 C122 C126 C130 C134 C138 C153 C159 C161 = CAP_NP: CAP NCS X5R 0402 2.2uF +/-20% 6.3V; Manufacturer: Samsung Electro-Mechanics Co., Ltd.; Manufacturer Part Number: CL05A225MQ5NNNC; Part Number: CL05A225MQ5NNNC; Part type: Ceramic; Tolerance: 20%; Voltage: 6.3V
U1 = LFCPNX-100-LFG672_4
C49 = CAP_NP: 1 µF ±10% 25V Ceramic Capacitor X5R 0402 (1005 Metric); Manufacturer: Murata; Manufacturer Part Number: GRM155R61E105KA12D; Part Number: GRM155R61E105KA12D; Part type: Ceramic; Tolerance: 10%; Voltage: 25V; Datasheet: https://www.digikey.com/en/htmldatasheets/production/2354729/0/0/1/grm155r61e105ka12x-ref-sheet.html?site=US&lang=en&cur=USD
R5-R12 = R: RES 0402 1.15kohm 1% 62.5mW; Manufacturer: Vishay Americas Inc.; Manufacturer Part Number: CRCW04021K15FKED; Part Number: CRCW04021K15FKED; Part type: Thick Film; Power: 62.5mW; Tolerance: 1%
R183 R184 = R: 49.9 Ohms ±1% 0.063W, 1/16W Chip Resistor 0402 (1005 Metric) Moisture Resistant Thick Film; Manufacturer: Yageo; Manufacturer Part Number: RC0402FR-0749R9L; Part Number: RC0402FR-0749R9L; Part type: Thick Film; Power: 1/16W; Tolerance: 1%; Datasheet: https://www.yageo.com/upload/media/product/app/datasheet/rchip/pyu-rc_group_51_rohs_l.pdf
Y1 = SIT9375: MEMS, Differential OSC XO, 161.132813 MHz, HCSL, 6-SMD, No Lead; Manufacturer: SiTime Corporation; Part Type: Oscillator; Datasheet: https://www.sitime.com/support/resource-library/datasheets/sit9375-datasheet

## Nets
GND: C6.2 C8.2 C9.2 C10.2 C11.2 C12.2 C13.2 C14.2 C15.2 C16.2 C17.2 C18.2 C19.2 C20.2 C21.2 C22.2 C23.2 C24.2 C25.2 C26.2 C27.2 C28.2 C29.2 C30.2 C31.2 C32.2 C33.2 C34.2 C35.2 C36.2 C37.2 C38.2 C40.2 C41.2 C43.2 C44.2 C46.2 C47.2 C49.2 C50.2 C51.2 C52.2 C55.2 C56.2 C57.2 C62.2 C63.2 C68.2 C69.2 C74.2 C75.2 C80.2 C81.2 C86.2 C87.2 C92.2 C93.2 C98.2 C99.2 C102.2 C103.2 C104.2 C105.2 C106.2 C107.2 C108.2 C109.2 C110.2 C111.2 C112.2 C113.2 C114.2 C115.2 C116.2 C117.2 C118.2 C119.2 C120.2 C121.2 C122.2 C123.2 C124.2 C125.2 C126.2 C127.2 C128.2 C129.2 C130.2 C131.2 C132.2 C133.2 C134.2 C135.2 C136.2 C137.2 C138.2 C139.2 C140.2 C141.2 C142.2 C143.2 C144.2 C145.2 C146.2 C147.2 C148.2 C149.2 C150.2 C151.2 C152.2 C153.2 C154.2 C155.2 C156.2 C157.2 C158.2 C159.2 C160.2 C161.2 C162.2 C163.2 C164.2 C341.2 C342.2 C343.2 C358.2 J20.1 J20.2 J20.19 J20.20 Q4.2(SOURCE) Q5.1(S1) Q5.4(S2) R158.2 R183.2 R184.2 R204.1 U1.A4(VSSSDQ) U1.A7(VSSSDQ) U1.A10(VSSSDQ) U1.A13(VSSSDQ) U1.A16(VSSSDQ) U1.A19(VSSSDQ) U1.A20(VSSSDQ) U1.A23(VSSSDQ) U1.AB21(VSS) U1.AC5(VSS) U1.AC8(VSS) U1.AC10(VSS) U1.AC14(VSS) U1.AC17(VSS) U1.AD2(VSSADC) U1.AD24(VSS) U1.AE20(VSS) U1.B2(VSSSDQ) U1.B3(VSSSDQ) U1.B5(VSSSDQ) U1.B6(VSSSDQ) U1.B8(VSSSDQ) U1.B9(VSSSDQ) U1.B11(VSSSDQ) U1.B12(VSSSDQ) U1.B14(VSSSDQ) U1.B15(VSSSDQ) U1.B17(VSSSDQ) U1.B18(VSSSDQ) U1.B21(VSSSDQ) U1.B22(VSSSDQ) U1.B24(VSSSDQ) U1.B25(VSSSDQ) U1.C2(VSSSDQ) U1.C3(VSSSDQ) U1.C5(VSSSDQ) U1.C7(VSSSDQ) U1.C9(VSSSDQ) U1.C11(VSSSDQ) U1.C13(VSSSDQ) U1.C15(VSSSDQ) U1.C17(VSSSDQ) U1.C19(VSSSDQ) U1.C20(VSSSDQ) U1.C23(VSSSDQ) U1.C25(VSSSDQ) U1.D1(VSSSDQ) U1.D4(VSSSDQ) U1.D6(VSSSDQ) U1.D7(VSSSDQ) U1.D8(VSSSDQ) U1.D10(VSSSDQ) U1.D12(VSSSDQ) U1.D14(VSSSDQ) U1.D16(VSSSDQ) U1.D20(VSSSDQ) U1.D21(VSSSDQ) U1.D22(VSSSDQ) U1.D23(VSSSDQ) U1.D24(VSSSDQ) U1.D25(SD1_RXDN) U1.D26(VSSSDQ) U1.E2(VSSSDQ) U1.E3(VSSSDQ) U1.E5(VSSSDQ) U1.E14(VSSSDQ) U1.E23(VSSSDQ) U1.E24(SD1_RXDP) U1.E25(VSSSDQ) U1.F2(VSSSDQ) U1.F4(VSSSDQ) U1.F5(VSSSDQ) U1.F6(VSSSDQ) U1.F7(VSSSDQ) U1.F8(VSSSDQ) U1.F10(VSSSDQ) U1.F13(VSSSDQ) U1.F14(VSSSDQ) U1.F18(VSSSDQ) U1.F21(VSSSDQ) U1.F23(VSSSDQ) U1.F24(VSSSDQ) U1.F25(VSSSDQ) U1.G1(VSSSDQ) U1.G3(VSSSDQ) U1.G10(VSSSDQ) U1.G12(VSSSDQ) U1.G14(VSSSDQ) U1.G16(VSSSDQ) U1.G23(VSSSDQ) U1.G24(SD0_RXDP) U1.G25(SD0_RXDN) U1.G26(VSSSDQ) U1.H14(VSSSDQ) U1.H18(VSSSDQ) U1.H24(VSSSDQ) U1.H25(VSSSDQ) U1.J4(VSS) U1.J11(VSSSDQ) U1.J12(VSSSDQ) U1.J17(VSSSDQ) U1.K13(VSSSDQ) U1.K23(VSS) U1.L4(VSS) U1.L11(VSS) U1.L13(VSS) U1.L16(VSSSDQ) U1.M11(VSS) U1.M13(VSS) U1.M15(VSS) U1.M17(VSS) U1.M21(VSS) U1.N10(VSS) U1.N12(VSS) U1.N14(VSS) U1.N16(VSS) U1.P4(VSS) U1.P11(VSS) U1.P13(VSS) U1.P15(VSS) U1.P17(VSS) U1.R10(VSS) U1.R12(VSS) U1.R14(VSS) U1.R16(VSS) U1.R24(VSS) U1.T11(VSS) U1.T13(VSS) U1.T15(VSS) U1.T17(VSS) U1.U5(VSS) U1.U9(VSS) U1.U12(VSS) U1.U14(VSS) U1.U16(VSS) U1.U21(VSS) U1.V11(VSS) U1.V13(VSS) U1.Y3(VSS) U1.Y24(VSS) U2.4(GND) U2.9(EPAD) U24.1(A0) U24.2(A1) U24.3(A2) U24.4(GND) U24.7(WP) U24.9(EP) Y1.3(GND) Y6.2(GND) ; also on sheet 9 10 11 12 13 14 15 16 17 18 19
VCCAUXSDQ0_CPRO: C58.1 C64.1 C70.1 C76.1 C82.1 C88.1 C94.1 C100.1 LB2.2 U1.J16(VCCAUXSDQ0)
VCCAUXSDQ1_CPRO: C59.1 C65.1 C71.1 C77.1 C83.1 C89.1 C95.1 C101.1 LB7.2 U1.J13(VCCAUXSDQ1)
VCCPLLSD0_CPRO: C53.1 C60.1 LB3.2 U1.F22(VCCPLLSD0)
VCCPLLSD1_CPRO: C66.1 C72.1 LB4.2 U1.G22(VCCPLLSD1)
VCCPLLSD2_CPRO: C78.1 C84.1 LB5.2 U1.F19(VCCPLLSD2)
VCCPLLSD3_CPRO: C90.1 C96.1 LB6.2 U1.E18(VCCPLLSD3)
VCCPLLSD4_CPRO: C54.1 C61.1 LB8.2 U1.E16(VCCPLLSD4)
VCCPLLSD5_CPRO: C67.1 C73.1 LB9.2 U1.H15(VCCPLLSD5)
VCCPLLSD6_CPRO: C79.1 C85.1 LB10.2 U1.F15(VCCPLLSD6)
VCCPLLSD7_CPRO: C91.1 C97.1 LB11.2 U1.F12(VCCPLLSD7)
VCCSDCK_CPRO: C52.1 C57.1 LB1.1 U1.M16(VCCSDCK)
VDD_1V0: C106.1 C107.1 C108.1 C109.1 C110.1 C111.1 C112.1 C113.1 C114.1 C115.1 C116.1 C117.1 C118.1 C119.1 C120.1 C121.1 C122.1 C123.1 C124.1 C125.1 C126.1 C127.1 C128.1 C129.1 C130.1 C131.1 C132.1 C133.1 C134.1 C135.1 C136.1 C137.1 C138.1 C139.1 C140.1 C141.1 C142.1 C143.1 C144.1 C145.1 C146.1 U1.L10(VCC) U1.L15(VCC) U1.M12(VCC) U1.M14(VCC) U1.N11(VCC) U1.N13(VCC) U1.N15(VCC) U1.N17(VCC) U1.P10(VCC) U1.P12(VCC) U1.P14(VCC) U1.P16(VCC) U1.R11(VCC) U1.R13(VCC) U1.R15(VCC) U1.T9(VCCECLK) U1.T10(VCC) U1.T12(VCC) U1.T14(VCC) U1.T16(VCC) U1.U11(VCC) U1.U13(VCC) U1.V12(VCCECLK) U1.V14(VCCECLK) U1.V16(VCCECLK) ; also on sheet 11 18
VDD_1V0_LDO: C50.1 C51.1 C55.1 C56.1 C62.1 C63.1 C68.1 C69.1 C74.1 C75.1 C80.1 C81.1 C86.1 C87.1 C92.1 C93.1 C98.1 C99.1 C102.1 C103.1 C104.1 C105.1 LB1.2 U1.F16(VCCSD4) U1.F17(VCCSD4) U1.G13(VCCSD7) U1.G15(VCCSD5) U1.G17(VCCSD3) U1.G18(VCCSD1) U1.G19(VCCSD0) U1.H13(VCCSD7) U1.H16(VCCSD5) U1.H17(VCCSD3) U1.H19(VCCSD0) U1.J14(VCCSD6) U1.J18(VCCSD1) U1.K14(VCCSD6) U1.K16(VCCSD2) U1.K17(VCCSD2) ; also on sheet 10 19
VDD_1V8: C6.1 C8.1 C9.1 C10.1 C11.1 C12.1 C13.1 C14.1 C15.1 C16.1 C17.1 C18.1 C19.1 C20.1 C21.1 C22.1 C23.1 C24.1 C25.1 C26.1 C27.1 C28.1 C29.1 C30.1 C31.1 C32.1 C33.1 C34.1 C35.1 C36.1 C37.1 C40.1 C43.1 C46.1 C358.1 R124.1 R126.1 R127.1 R159.1 R180.1 R181.1 U1.AA3(VCCIO2) U1.AA21(VCCIO5) U1.AB5(VCCIO3) U1.AB8(VCCIO3) U1.AB10(VCCIO3) U1.AB14(VCCIO4) U1.AB17(VCCIO4) U1.AC23(VCCIO5) U1.AD19(VCCIO4) U1.H5(VCCIO0) U1.L5(VCCIO1) U1.P5(VCCIO1) U1.R23(VCCIO6) U1.U4(VCCIO2) U1.U20(VCCIO6) U1.Y23(VCCIO5) U2.8(VCC) U24.8(VCC) ; also on sheet 9 10 11 13 14 16 17 18 19
VDD_1V8_CAM: R148.1 R149.1 R150.1 R151.1 R152.1 R153.1 ; also on sheet 12 19
VDD_1V8_CPRO_ADC: C342.1 C343.1 LB43.2 U1.AC1(ADC_REFP0) U1.AC2(ADC_REFP1) U1.AC3(VCCADC18)
VDD_1V8_CPRO_CLK: C341.1 R181.2 Y6.4(VCC)
VDD_1V8_CPRO_VCCAUX: C148.1 C149.1 C151.1 C152.1 C154.1 C155.1 C157.1 C158.1 C159.1 C160.1 C161.1 C162.1 C163.1 C164.1 LB13.1 U1.L17(VCCAUX) U1.M10(VCCAUX) U1.R17(VCCAUX) U1.U10(VCCAUX) U1.U15(VCCAUXH4) U1.U17(VCCAUXH5) U1.V9(VCCAUXH3) U1.V10(VCCAUXH3) U1.V15(VCCAUXH4) U1.V17(VCCAUXH5)
VDD_1V8_CPRO_VCCAUXA: C147.1 C150.1 C153.1 C156.1 LB12.1 U1.L12(VCCAUXA) U1.L14(VCCAUXA)
VDD_1V8_LDO: LB2.1 LB3.1 LB4.1 LB5.1 LB6.1 LB7.1 LB8.1 LB9.1 LB10.1 LB11.1 LB12.2 LB13.2 LB43.1 ; also on sheet 10 19
VDD_2V5_ETH_OSC: C49.1 LB42.1 R4.1 Y1.6(VCC)
VDD_2V5_LDO: LB42.2 ; also on sheet 19
VDD_3V3: C38.1 C41.1 C44.1 C47.1 DS1.2(ANODE) DS3.2(ANODE) U1.K22(VCCIO7) U1.M20(VCCIO7) ; also on sheet 9 13 14 15 16 17 18 19
CLK_SYNTH_LOCK: U1.R7(PR29B) ; also on sheet 16
CLK_SYNTH_OE: U1.P8(PR26B) ; also on sheet 16
CLNK_LVDS_0_N: U1.AF13(PB102B/ADC_CN6) ; also on sheet 9
CLNK_LVDS_0_P: U1.AF14(PB102A/ADC_CP6) ; also on sheet 9
CLNK_LVDS_1_N: U1.AD18(PB80B) ; also on sheet 9
CLNK_LVDS_1_P: U1.AC18(PB80A) ; also on sheet 9
CLNK_LVDS_2_N: U1.AC15(PB86B) ; also on sheet 9
CLNK_LVDS_2_P: U1.AB15(PB86A) ; also on sheet 9
CLNK_LVDS_3_N: U1.AE14(PB96B) ; also on sheet 9
CLNK_LVDS_3_P: U1.AD14(PB96A) ; also on sheet 9
CLNK_LVDS_4_N: U1.AC24(PB34B) ; also on sheet 10
CLNK_LVDS_4_P: U1.AB25(PB34A) ; also on sheet 10
CLNK_LVDS_5_N: U1.AB20(PB48B/VREF5_2) ; also on sheet 10
CLNK_LVDS_5_P: U1.AC20(PB48A) ; also on sheet 10
CLNK_LVDS_6_N: U1.AD26(PB36B) ; also on sheet 10
CLNK_LVDS_6_P: U1.AC25(PB36A) ; also on sheet 10
CLNK_LVDS_7_N: U1.AE23(PB50B) ; also on sheet 10
CLNK_LVDS_7_P: U1.AE22(PB50A/VREF4_1) ; also on sheet 10
CLNK_LVDS_8_N: U1.AD23(PB38B) ; also on sheet 10
CLNK_LVDS_8_P: U1.AC22(PB38A) ; also on sheet 10
CLNK_LVDS_9_N: U1.AF25(PB42B) ; also on sheet 10
CLNK_LVDS_9_P: U1.AE26(PB42A) ; also on sheet 10
CLNK_LVDS_10_N: U1.AF23(PB54B) ; also on sheet 10
CLNK_LVDS_10_P: U1.AF22(PB54A) ; also on sheet 10
CLNK_LVDS_11_N: U1.AB26(PB30B) ; also on sheet 10
CLNK_LVDS_11_P: U1.AC26(PB30A) ; also on sheet 10
CLNK_LVDS_CC_0_N: U1.AE12(PB106B/PCLKC4_3) ; also on sheet 9
CLNK_LVDS_CC_0_P: U1.AE13(PB106A/PCLKT4_3) ; also on sheet 9
CLNK_LVDS_CC_1_N: U1.AE15(PB88B) ; also on sheet 9
CLNK_LVDS_CC_1_P: U1.AD15(PB88A) ; also on sheet 9
CLNK_LVDS_CC_2_N: U1.AD13(PB104B/ADC_CN9) ; also on sheet 9
CLNK_LVDS_CC_2_P: U1.AC13(PB104A/ADC_CP9) ; also on sheet 9
CLNK_LVDS_CC_3_N: U1.AB13(PB100B/PCLKC4_2/ADC_CN7) ; also on sheet 9
CLNK_LVDS_CC_3_P: U1.AA13(PB100A/PCLKT4_2/ADC_CP7) ; also on sheet 9
CLNK_LVDS_CC_4_N: U1.AB24(PB32B) ; also on sheet 10
CLNK_LVDS_CC_4_P: U1.AB23(PB32A) ; also on sheet 10
CLNK_LVDS_CC_5_N: U1.AC19(PB56B) ; also on sheet 10
CLNK_LVDS_CC_5_P: U1.AD20(PB56A) ; also on sheet 10
CLNK_LVDS_CC_6_N: U1.AF24(PB44B) ; also on sheet 10
CLNK_LVDS_CC_6_P: U1.AE24(PB44A) ; also on sheet 10
CLNK_LVDS_CC_7_N: U1.AA18(PB60B) ; also on sheet 10
CLNK_LVDS_CC_7_P: U1.Y18(PB60A) ; also on sheet 10
CLNK_LVDS_CC_8_N: U1.AD22(PB46B/PCLKC5_3) ; also on sheet 10
CLNK_LVDS_CC_8_P: U1.AC21(PB46A/PCLKT5_3) ; also on sheet 10
CLNK_LVDS_CC_9_N: U1.AB18(PB58B/PCLKC4_1) ; also on sheet 10
CLNK_LVDS_CC_9_P: U1.AB19(PB58A/PCLKT4_1) ; also on sheet 10
CLNK_LVDS_CC_10_N: U1.AE25(PB40B/PCLKC5_2) ; also on sheet 10
CLNK_LVDS_CC_10_P: U1.AD25(PB40A/PCLKT5_2) ; also on sheet 10
CLNK_LVDS_CC_11_N: U1.AE21(PB52B/PCLKC4_0) ; also on sheet 10
CLNK_LVDS_CC_11_P: U1.AD21(PB52A/PCLKT4_0) ; also on sheet 10
CPCL_GPIO_0: U1.R5(PR28B) ; also on sheet 9
CPCL_GPIO_1: U1.P9(PR26A) ; also on sheet 9
CPRO_ADC_DN0: TP2.1(TP) U1.AE2(ADC_DN0)
CPRO_ADC_DN1: TP4.1(TP) U1.AD1(ADC_DN1)
CPRO_ADC_DP0: TP1.1(TP) U1.AF2(ADC_DP0)
CPRO_ADC_DP1: TP3.1(TP) U1.AE1(ADC_DP1)
CPRO_CAM_1V8_EN: U1.N6(PR22A) ; also on sheet 19
CPRO_CAM_2V8_EN: U1.N5(PR20B) ; also on sheet 19
CPRO_CAM_3V3_EN: U1.N7(PR22B) ; also on sheet 19
CPRO_CAM_GPIO_0: U1.T25(PL53B) ; also on sheet 12
CPRO_CAM_GPIO_1: U1.T24(PL55A) ; also on sheet 12
CPRO_CAM_GPIO_2: U1.T23(PL55B) ; also on sheet 12
CPRO_CAM_GPIO_3: U1.T21(PL56A) ; also on sheet 12
CPRO_CAM_GPIO_4: U1.T20(PL56B) ; also on sheet 12
CPRO_CAM_GPIO_5: U1.T19(PL58A) ; also on sheet 12
CPRO_CAM_GPIO_6: U1.T18(PL58B) ; also on sheet 12
CPRO_CAM_GPIO_7: U1.U19(PL60A) ; also on sheet 12
CPRO_CAM_GPIO_8: U1.U18(PL60B) ; also on sheet 12
CPRO_CAM_GPIO_9: U1.U22(PL62A) ; also on sheet 12
CPRO_CAM_I2C0_SCL: R153.2 U1.P22(PL44A/PCLKT6_1) ; also on sheet 12
CPRO_CAM_I2C0_SDA: R152.2 U1.P21(PL44B) ; also on sheet 12
CPRO_CAM_I2C1_SCL: R151.2 U1.R20(PL46A/PCLKT6_2) ; also on sheet 12
CPRO_CAM_I2C1_SDA: R150.2 U1.R21(PL46B) ; also on sheet 12
CPRO_CAM_I2C2_SCL: R149.2 U1.R18(PL47B) U1.R19(PL47A) ; also on sheet 12
CPRO_CAM_I2C2_SDA: R148.2
CPRO_CAM_SPI_MCS_N: U1.P23(PL42B) ; also on sheet 12
CPRO_CAM_SPI_MISO: U1.P24(PL42A/PCLKT6_0) ; also on sheet 12
CPRO_CAM_SPI_MOSI: U1.P25(PL40B) ; also on sheet 12
CPRO_CAM_SPI_MSCK: U1.P26(PL40A) ; also on sheet 12
CPRO_CAM_UART_CTS: U1.T26(PL53A) ; also on sheet 12
CPRO_CAM_UART_RTS: U1.R26(PL51B) ; also on sheet 12
CPRO_CAM_UART_TX: U1.R25(PL51A) ; also on sheet 12
CPRO_CTRL_I2C_SCL: U1.M3(PR15A) U24.6(SCL) ; also on sheet 16
CPRO_CTRL_I2C_SDA: U1.M2(PR15B) U24.5(SDA) ; also on sheet 16
CPRO_CTRL_SPI_MCLK: U1.N2(PR19A) ; also on sheet 9
CPRO_CTRL_SPI_MCS_N: U1.N1(PR17B) ; also on sheet 9
CPRO_CTRL_SPI_MISO: U1.M1(PR17A) ; also on sheet 9
CPRO_CTRL_SPI_MOSI: U1.N3(PR19B) ; also on sheet 9
CPRO_DONE: Q4.1(GATE) R124.2 U1.G5(PT136B/DONE)
CPRO_DONE_N_LED: DS3.1(CATHODE) R128.1
CPRO_DONE_N_LED_R: Q4.3(DRAIN) R128.2
CPRO_ETH_REFCLK_EN: R4.2 Y1.1(OE)
CPRO_ETH_REFCLK_N: R184.1 U1.E20(SDQ0_REFCLKN) Y1.5(OUTN)
CPRO_ETH_REFCLK_P: R183.1 U1.F20(SDQ0_REFCLKP) Y1.4(OUTP)
CPRO_FLASH_QSPI_MCLK: R1.1 R158.1 R159.2 U1.G6(PT136A/MCLK/PCLKT0_0)
CPRO_FLASH_QSPI_MCS_N: U1.G7(PT138A/MCSN/PCLKT0_1) U2.1(*CS)
CPRO_FLASH_QSPI_MD0: U1.H7(PT138B/MOSI/MD0) U2.5(DI(IO0))
CPRO_FLASH_QSPI_MD1: U1.H6(PT140A/MISO/MD1/OSC_HI) U2.2(DO(IO1))
CPRO_FLASH_QSPI_MD2: R204.2 U1.K5(PT140B/MD2) U2.3(*WP(IO2))
CPRO_FLASH_QSPI_MD3: U1.H4(PT142A/MD3) U2.7(*HOLD(IO3))
CPRO_FMC_CLK0_M2C_N: U1.AD12(PB112B/PCLKC3_0/ADC_CN4) ; also on sheet 13
CPRO_FMC_CLK0_M2C_P: U1.AC12(PB112A/PCLKT3_0/ADC_CP4) ; also on sheet 13
CPRO_FMC_CLK1_M2C_N: U1.AC11(PB118B/PCLKC3_1/COMP2IN) ; also on sheet 13
CPRO_FMC_CLK1_M2C_P: U1.AB11(PB118A/PCLKT3_1/COMP2IP) ; also on sheet 13
CPRO_FMC_CLK3_BIDIR_N: U1.W23(PB10B/PCLKC5_1/ADC_CN2/COMP3N) ; also on sheet 13
CPRO_FMC_CLK3_BIDIR_P: U1.W24(PB10A/PCLKT5_1/ADC_CP2/COMP3P) ; also on sheet 13
CPRO_FMC_CLK_DIR_1V8: U1.W1(PR60A) ; also on sheet 14
CPRO_FMC_GA0_1V8: U1.W2(PR58B) ; also on sheet 14
CPRO_FMC_GA1_1V8: U1.W5(PR56A) ; also on sheet 14
CPRO_FMC_GBTCLK0_N: U1.E11(SD_EXT0_REFCLKN) ; also on sheet 13
CPRO_FMC_GBTCLK0_P: U1.D11(SD_EXT0_REFCLKP) ; also on sheet 13
CPRO_FMC_GBTCLK1_N: U1.D9(SD_EXT1_REFCLKN) ; also on sheet 13
CPRO_FMC_GBTCLK1_P: U1.E10(SD_EXT1_REFCLKP) ; also on sheet 13
CPRO_FMC_I2C_SCL_1V8: U1.Y4(PR62A) ; also on sheet 14
CPRO_FMC_I2C_SDA_1V8: U1.AA4(PR62B) ; also on sheet 14
CPRO_FMC_LA00_CC_N: U1.Y5(PB148A/PCLKT3_2/COMP3IP) ; also on sheet 13
CPRO_FMC_LA00_CC_P: U1.AA5(PB148B/PCLKC3_2/COMP3IN) ; also on sheet 13
CPRO_FMC_LA01_CC_N: U1.AB4(PB154A/PCLKT3_3/ADC_CP15) ; also on sheet 13
CPRO_FMC_LA01_CC_P: U1.AC4(PB154B/PCLKC3_3/ADC_CN15) ; also on sheet 13
CPRO_FMC_LA02_N: U1.AB12(PB110B/ADC_CN10) ; also on sheet 13
CPRO_FMC_LA02_P: U1.AA12(PB110A/VREF3_1/ADC_CP10) ; also on sheet 13
CPRO_FMC_LA03_N: U1.AF11(PB114B/COMP1IN) ; also on sheet 13
CPRO_FMC_LA03_P: U1.AF12(PB114A/COMP1IP) ; also on sheet 13
CPRO_FMC_LA04_N: U1.AE11(PB116B/ADC_CN8) ; also on sheet 13
CPRO_FMC_LA04_P: U1.AD11(PB116A/ADC_CP8) ; also on sheet 13
CPRO_FMC_LA05_N: U1.AA11(PB120B/ADC_CN13) ; also on sheet 13
CPRO_FMC_LA05_P: U1.Y11(PB120A/ADC_CP13) ; also on sheet 13
CPRO_FMC_LA06_N: U1.W10(PB122B) ; also on sheet 13
CPRO_FMC_LA06_P: U1.W11(PB122A) ; also on sheet 13
CPRO_FMC_LA07_N: U1.AA10(PB124B) ; also on sheet 13
CPRO_FMC_LA07_P: U1.Y10(PB124A) ; also on sheet 13
CPRO_FMC_LA08_N: U1.AF9(PB126B) ; also on sheet 13
CPRO_FMC_LA08_P: U1.AF10(PB126A) ; also on sheet 13
CPRO_FMC_LA09_N: U1.AE10(PB128B) ; also on sheet 13
CPRO_FMC_LA09_P: U1.AD10(PB128A) ; also on sheet 13
CPRO_FMC_LA10_N: U1.AE9(PB130B) ; also on sheet 13
CPRO_FMC_LA10_P: U1.AD9(PB130A) ; also on sheet 13
CPRO_FMC_LA11_N: U1.AC9(PB132B) ; also on sheet 13
CPRO_FMC_LA11_P: U1.AB9(PB132A) ; also on sheet 13
CPRO_FMC_LA12_N: U1.AB7(PB134B) ; also on sheet 13
CPRO_FMC_LA12_P: U1.AC7(PB134A) ; also on sheet 13
CPRO_FMC_LA13_N: U1.Y7(PB136B) ; also on sheet 13
CPRO_FMC_LA13_P: U1.AA7(PB136A) ; also on sheet 13
CPRO_FMC_LA14_N: U1.AF5(PB138B) ; also on sheet 13
CPRO_FMC_LA14_P: U1.AF6(PB138A) ; also on sheet 13
CPRO_FMC_LA15_N: U1.AE6(PB140B) ; also on sheet 13
CPRO_FMC_LA15_P: U1.AD6(PB140A) ; also on sheet 13
CPRO_FMC_LA16_N: U1.AC6(PB142B) ; also on sheet 13
CPRO_FMC_LA16_P: U1.AB6(PB142A) ; also on sheet 13
CPRO_FMC_LA17_N: U1.AE5(PB144B) ; also on sheet 13
CPRO_FMC_LA17_P: U1.AD5(PB144A) ; also on sheet 13
CPRO_FMC_LA18_N: U1.AA6(PB146B/ADC_CN14) ; also on sheet 13
CPRO_FMC_LA18_P: U1.Y6(PB146A/ADC_CP14) ; also on sheet 13
CPRO_FMC_LA19_N: U1.AF3(PB150B/ADC_CN11) ; also on sheet 13
CPRO_FMC_LA19_P: U1.AF4(PB150A/ADC_CP11) ; also on sheet 13
CPRO_FMC_LA20_N: U1.AE4(PB152B/ADC_CN12) ; also on sheet 13
CPRO_FMC_LA20_P: U1.AD4(PB152A/ADC_CP12) ; also on sheet 13
CPRO_FMC_LA21_N: U1.AE3(PB156B/LRC_GPLL0C_IN/VREF3_2) ; also on sheet 13
CPRO_FMC_LA21_P: U1.AD3(PB156A/LRC_GPLL0T_IN) ; also on sheet 13
CPRO_FMC_LA22_N: U1.AF20(PB66B) ; also on sheet 13
CPRO_FMC_LA22_P: U1.AF21(PB66A) ; also on sheet 13
CPRO_FMC_LA23_N: U1.W21(PB12B) ; also on sheet 13
CPRO_FMC_LA23_P: U1.W22(PB12A) ; also on sheet 13
CPRO_FMC_LA24_N: U1.W16(PB84B) ; also on sheet 13
CPRO_FMC_LA24_P: U1.Y16(PB84A) ; also on sheet 13
CPRO_FMC_LA25_N: U1.W18(PB62B) ; also on sheet 13
CPRO_FMC_LA25_P: U1.W17(PB62A) ; also on sheet 13
CPRO_FMC_LA26_N: U1.AE19(PB64B) ; also on sheet 13
CPRO_FMC_LA26_P: U1.AF19(PB64A) ; also on sheet 13
CPRO_FMC_LA27_N: U1.Y17(PB82B) ; also on sheet 13
CPRO_FMC_LA27_P: U1.AA17(PB82A) ; also on sheet 13
CPRO_FMC_LA28_N: U1.W14(PB92B) ; also on sheet 13
CPRO_FMC_LA28_P: U1.W15(PB92A) ; also on sheet 13
CPRO_FMC_LA29_N: U1.AF16(PB90B) ; also on sheet 13
CPRO_FMC_LA29_P: U1.AF15(PB90A) ; also on sheet 13
CPRO_FMC_LA30_N: U1.Y13(PB98B/ADC_CN5) ; also on sheet 13
CPRO_FMC_LA30_P: U1.W13(PB98A/ADC_CP5) ; also on sheet 13
CPRO_FMC_LA31_N: U1.AA14(PB94B) ; also on sheet 13
CPRO_FMC_LA31_P: U1.Y14(PB94A) ; also on sheet 13
CPRO_FMC_LA32_N: U1.V22(PB4B/PCLKC5_0/CDR_RXN1/ADC_CN1/COMP2N) ; also on sheet 13
CPRO_FMC_LA32_P: U1.V23(PB4A/PCLKT5_0/CDR_RXP1/ADC_CP1/COMP2P) ; also on sheet 13
CPRO_FMC_LA33_N: U1.W12(PB108B/VREF4_2) ; also on sheet 13
CPRO_FMC_LA33_P: U1.Y12(PB108A) ; also on sheet 13
CPRO_FMC_PG_M2C_1V8: U1.Y1(PR60B) ; also on sheet 14
CPRO_FMC_PRSNT_N: U1.W3(PR58A) ; also on sheet 13 14
CPRO_FPGA_SYNC_IN: U1.U23(PL62B) ; also on sheet 14
CPRO_FPGA_SYNC_OUT: U1.U24(PL64A) ; also on sheet 14
CPRO_INIT: Q5.5(G2) Q5.6(D1) R127.2
CPRO_INIT_N: Q5.2(G1) R126.2 U1.G2(PT134A/INITN)
CPRO_INIT_N_LED: DS1.1(CATHODE) R125.1
CPRO_INIT_N_LED_R: Q5.3(D2) R125.2
CPRO_JESD_REFCLK_N: U1.D13(SDQ1_REFCLKN) ; also on sheet 16
CPRO_JESD_REFCLK_P: U1.C14(SDQ1_REFCLKP) ; also on sheet 16
CPRO_JESD_SYSREF_N: U1.V26(PB6B) ; also on sheet 14
CPRO_JESD_SYSREF_P: U1.U26(PB6A) ; also on sheet 14
CPRO_JTAG_TDI: U1.L9(PR8B/TDI/SSI) ; also on sheet 17
CPRO_JTAG_TDO: U1.M8(PR10B/TDO/SSO) ; also on sheet 17
CPRO_MCLK_BUF_OE_N: U1.N8(PR24B) ; also on sheet 16
CPRO_PCLK: R182.2 U1.R4(PR28A/PCLKT1_2)
CPRO_PCLK_EN: R180.2 Y6.1(EN)
CPRO_PCLK_R: R182.1 Y6.3(OUT)
CPRO_SD0_REXT: R5.1 U1.E21(SD0_REXT)
CPRO_SD1_REXT: R7.1 U1.G20(SD1_REXT)
CPRO_SD2_REXT: R9.1 U1.D19(SD2_REXT)
CPRO_SD3_REXT: R11.1 U1.C18(SD3_REXT)
CPRO_SD4_REXT: R6.1 U1.D17(SD4_REXT)
CPRO_SD5_REXT: R8.2 U1.K15(SD5_REXT)
CPRO_SD6_REXT: R10.2 U1.D15(SD6_REXT)
CPRO_SD7_REXT: R12.2 U1.E13(SD7_REXT)
CPRO_TEST_POINT_0: J20.3 U1.J19(PL13A)
CPRO_TEST_POINT_1: J20.5 U1.K20(PL13B)
CPRO_TEST_POINT_2: J20.7 U1.K18(PL15A)
CPRO_TEST_POINT_3: J20.9 U1.K19(PL15B)
CPRO_TEST_POINT_4: J20.11 U1.K21(PL17A)
CPRO_TEST_POINT_5: J20.13 U1.L21(PL17B)
CPRO_TEST_POINT_6: J20.15 U1.K24(PL19A)
CPRO_TEST_POINT_7: J20.17 U1.K25(PL19B)
CPRO_TEST_POINT_8: J20.4 U1.K26(PL20A)
CPRO_TEST_POINT_9: J20.6 U1.L26(PL20B)
CPRO_TEST_POINT_10: J20.8 U1.L25(PL22A)
CPRO_TEST_POINT_11: J20.10 U1.L24(PL22B)
CPRO_TEST_POINT_12: J20.12 U1.L23(PL24A)
CPRO_TEST_POINT_13: J20.14 U1.L22(PL24B)
CPRO_TEST_POINT_14: J20.16 U1.L20(PL26A)
CPRO_TEST_POINT_15: J20.18 U1.L19(PL26B)
ETH_RXD0_N: U1.B23(SD2_RXDN) ; also on sheet 15
ETH_RXD0_P: U1.C24(SD2_RXDP) ; also on sheet 15
ETH_RXD1_N: U1.C22(SD3_RXDN) ; also on sheet 15
ETH_RXD1_P: U1.C21(SD3_RXDP) ; also on sheet 15
ETH_TXD0_N: U1.A25(SD2_TXDP) ; also on sheet 15
ETH_TXD0_P: U1.A24(SD2_TXDN) ; also on sheet 15
ETH_TXD1_N: U1.A22(SD3_TXDP) ; also on sheet 15
ETH_TXD1_P: U1.A21(SD3_TXDN) ; also on sheet 15
FPGA_JTAG_EN: U1.K1(JTAG_EN) ; also on sheet 9 17
FPGA_JTAG_TCLK: U1.M5(PR13A/TCK/SCLK/PMU_EXT_CLK) ; also on sheet 9 17
FPGA_JTAG_TMS: U1.L7(PR6B/TMS/SCSN) ; also on sheet 9 17
FPGA_PROG_I2C_SCL: U1.M7(PR11B/SCL) ; also on sheet 9 17
FPGA_PROG_I2C_SDA: U1.M6(PR11A/SDA) ; also on sheet 9 17
FPGA_PROGRAM_N: U1.G4(PT134B/PROGRAMN) ; also on sheet 9 17
FPGA_RESET_N: U1.N9(PR24A) ; also on sheet 9 17
JESD_RXD0_N: U1.B10(SD7_RXDP) ; also on sheet 13
JESD_RXD0_P: U1.C10(SD7_RXDN) ; also on sheet 13
JESD_RXD1_N: U1.B13(SD6_RXDP) ; also on sheet 13
JESD_RXD1_P: U1.C12(SD6_RXDN) ; also on sheet 13
JESD_RXD2_N: U1.C16(SD5_RXDP) ; also on sheet 13
JESD_RXD2_P: U1.B16(SD5_RXDN) ; also on sheet 13
JESD_RXD3_N: U1.B20(SD4_RXDP) ; also on sheet 13
JESD_RXD3_P: U1.B19(SD4_RXDN) ; also on sheet 13
JESD_TXD0_N: U1.A9(SD7_TXDP) ; also on sheet 13
JESD_TXD0_P: U1.A8(SD7_TXDN) ; also on sheet 13
JESD_TXD1_N: U1.A12(SD6_TXDP) ; also on sheet 13
JESD_TXD1_P: U1.A11(SD6_TXDN) ; also on sheet 13
JESD_TXD2_N: U1.A15(SD5_TXDP) ; also on sheet 13
JESD_TXD2_P: U1.A14(SD5_TXDN) ; also on sheet 13
JESD_TXD3_N: U1.A18(SD4_TXDP) ; also on sheet 13
JESD_TXD3_P: U1.A17(SD4_TXDN) ; also on sheet 13
SD0_REF: C53.2 C58.2 C60.2 C64.2 R5.2 U1.E22(SD0_REFRET)
SD1_REF: C66.2 C70.2 C72.2 C76.2 R7.2 U1.G21(SD1_REFRET)
SD2_REF: C78.2 C82.2 C84.2 C88.2 R9.2 U1.E19(SD2_REFRET)
SD3_REF: C90.2 C94.2 C96.2 C100.2 R11.2 U1.D18(SD3_REFRET)
SD4_REF: C54.2 C59.2 C61.2 C65.2 R6.2 U1.E17(SD4_REFRET)
SD5_REF: C67.2 C71.2 C73.2 C77.2 R8.1 U1.J15(SD5_REFRET)
SD6_REF: C79.2 C83.2 C85.2 C89.2 R10.1 U1.E15(SD6_REFRET)
SD7_REF: C91.2 C95.2 C97.2 C101.2 R12.1 U1.E12(SD7_REFRET)
SFP0_ABS: U1.H26(PL6A) ; also on sheet 15
SFP0_I2C_SCL: U1.H23(PL4B) ; also on sheet 15
SFP0_I2C_SDA: U1.H22(PL4A) ; also on sheet 15
SFP0_LOS: U1.J26(PL6B) ; also on sheet 15
SFP0_TX_DISABLE: U1.H21(PL3B/ULC_GPLL0C_IN) ; also on sheet 15
SFP0_TX_FAULT: U1.H20(PL3A/ULC_GPLL0T_IN) ; also on sheet 15
SFP1_ABS: U1.J21(PL11A) ; also on sheet 15
SFP1_I2C_SCL: U1.J22(PL10B) ; also on sheet 15
SFP1_I2C_SDA: U1.J23(PL10A) ; also on sheet 15
SFP1_LOS: U1.J20(PL11B) ; also on sheet 15
SFP1_TX_DISABLE: U1.J24(PL8B) ; also on sheet 15
SFP1_TX_FAULT: U1.J25(PL8A) ; also on sheet 15
SNN_CPRO_CAM_I2C3_SDA: U1.R22(PL49A) U1.T22(PL49B)
SNN_CPRO_NC_A2: U1.A2(NC)
SNN_CPRO_NC_A3: U1.A3(NC)
SNN_CPRO_NC_A5: U1.A5(NC)
SNN_CPRO_NC_A6: U1.A6(NC)
SNN_CPRO_NC_AA8: U1.AA8(NC)
SNN_CPRO_NC_AA9: U1.AA9(NC)
SNN_CPRO_NC_AA15: U1.AA15(NC)
SNN_CPRO_NC_AA16: U1.AA16(NC)
SNN_CPRO_NC_AA19: U1.AA19(NC)
SNN_CPRO_NC_AA20: U1.AA20(NC)
SNN_CPRO_NC_AA25: U1.AA25(NC)
SNN_CPRO_NC_AA26: U1.AA26(NC)
SNN_CPRO_NC_AB16: U1.AB16(NC)
SNN_CPRO_NC_AC16: U1.AC16(NC)
SNN_CPRO_NC_AD7: U1.AD7(NC)
SNN_CPRO_NC_AD8: U1.AD8(NC)
SNN_CPRO_NC_AD16: U1.AD16(NC)
SNN_CPRO_NC_AD17: U1.AD17(NC)
SNN_CPRO_NC_AE7: U1.AE7(NC)
SNN_CPRO_NC_AE8: U1.AE8(NC)
SNN_CPRO_NC_AE16: U1.AE16(NC)
SNN_CPRO_NC_AE17: U1.AE17(NC)
SNN_CPRO_NC_AE18: U1.AE18(NC)
SNN_CPRO_NC_AF7: U1.AF7(NC)
SNN_CPRO_NC_AF8: U1.AF8(NC)
SNN_CPRO_NC_AF17: U1.AF17(NC)
SNN_CPRO_NC_AF18: U1.AF18(NC)
SNN_CPRO_NC_B1: U1.B1(NC)
SNN_CPRO_NC_B4: U1.B4(NC)
SNN_CPRO_NC_B7: U1.B7(NC)
SNN_CPRO_NC_C1: U1.C1(NC)
SNN_CPRO_NC_C4: U1.C4(NC)
SNN_CPRO_NC_C6: U1.C6(NC)
SNN_CPRO_NC_C8: U1.C8(NC)
SNN_CPRO_NC_D2: U1.D2(NC)
SNN_CPRO_NC_D3: U1.D3(NC)
SNN_CPRO_NC_D5: U1.D5(NC)
SNN_CPRO_NC_E1: U1.E1(NC)
SNN_CPRO_NC_E4: U1.E4(NC)
SNN_CPRO_NC_E6: U1.E6(NC)
SNN_CPRO_NC_E7: U1.E7(NC)
SNN_CPRO_NC_E8: U1.E8(NC)
SNN_CPRO_NC_E9: U1.E9(NC)
SNN_CPRO_NC_F1: U1.F1(NC)
SNN_CPRO_NC_F3: U1.F3(NC)
SNN_CPRO_NC_F9: U1.F9(NC)
SNN_CPRO_NC_F11: U1.F11(NC)
SNN_CPRO_NC_G8: U1.G8(NC)
SNN_CPRO_NC_G9: U1.G9(NC)
SNN_CPRO_NC_G11: U1.G11(NC)
SNN_CPRO_NC_H8: U1.H8(NC)
SNN_CPRO_NC_H9: U1.H9(NC)
SNN_CPRO_NC_H10: U1.H10(NC)
SNN_CPRO_NC_H11: U1.H11(NC)
SNN_CPRO_NC_H12: U1.H12(NC)
SNN_CPRO_NC_J8: U1.J8(NC)
SNN_CPRO_NC_J9: U1.J9(NC)
SNN_CPRO_NC_J10: U1.J10(NC)
SNN_CPRO_NC_K9: U1.K9(NC)
SNN_CPRO_NC_K10: U1.K10(NC)
SNN_CPRO_NC_K11: U1.K11(NC)
SNN_CPRO_NC_K12: U1.K12(NC)
SNN_CPRO_NC_L18: U1.L18(NC)
SNN_CPRO_NC_M18: U1.M18(NC)
SNN_CPRO_NC_M19: U1.M19(NC)
SNN_CPRO_NC_M22: U1.M22(NC)
SNN_CPRO_NC_M23: U1.M23(NC)
SNN_CPRO_NC_M24: U1.M24(NC)
SNN_CPRO_NC_M25: U1.M25(NC)
SNN_CPRO_NC_N18: U1.N18(NC)
SNN_CPRO_NC_P1: U1.P1(NC)
SNN_CPRO_NC_P2: U1.P2(NC)
SNN_CPRO_NC_P3: U1.P3(NC)
SNN_CPRO_NC_P6: U1.P6(NC)
SNN_CPRO_NC_P7: U1.P7(NC)
SNN_CPRO_NC_R1: U1.R1(NC)
SNN_CPRO_NC_R2: U1.R2(NC)
SNN_CPRO_NC_R3: U1.R3(NC)
SNN_CPRO_NC_W8: U1.W8(NC)
SNN_CPRO_NC_W9: U1.W9(NC)
SNN_CPRO_NC_W19: U1.W19(NC)
SNN_CPRO_NC_W20: U1.W20(NC)
SNN_CPRO_NC_Y8: U1.Y8(NC)
SNN_CPRO_NC_Y9: U1.Y9(NC)
SNN_CPRO_NC_Y15: U1.Y15(NC)
SNN_CPRO_NC_Y19: U1.Y19(NC)
SNN_CPRO_NC_Y20: U1.Y20(NC)
SNN_CPRO_NC_Y21: U1.Y21(NC)
SNN_CPRO_NC_Y22: U1.Y22(NC)
SNN_CPRO_NC_Y25: U1.Y25(NC)
SNN_CPRO_NC_Y26: U1.Y26(NC)
SNN_CPRO_PB2A: U1.V24(PB2A/LLC_GPLL0T_IN/CDR_RXP0/VREF5_1/ADC_CP0/COMP1P)
SNN_CPRO_PB2B: U1.V25(PB2B/LLC_GPLL0C_IN/CDR_RXN0/ADC_CN0/COMP1N)
SNN_CPRO_PB8A: U1.W25(PB8A/ADC_CP3)
SNN_CPRO_PB8B: U1.W26(PB8B/ADC_CN3)
SNN_CPRO_PB26A: U1.AB22(PB26A)
SNN_CPRO_PB26B: U1.AA22(PB26B)
SNN_CPRO_PB28A: U1.AA23(PB28A)
SNN_CPRO_PB28B: U1.AA24(PB28B)
SNN_CPRO_PL28A: U1.M26(PL28A/PCLKT7_2)
SNN_CPRO_PL28B: U1.N26(PL28B)
SNN_CPRO_PL29A: U1.N25(PL29A/PCLKT7_1)
SNN_CPRO_PL29B: U1.N24(PL29B)
SNN_CPRO_PL31A: U1.N23(PL31A/PCLKT7_0)
SNN_CPRO_PL31B: U1.N22(PL31B)
SNN_CPRO_PL33A: U1.N21(PL33A)
SNN_CPRO_PL33B: U1.N20(PL33B)
SNN_CPRO_PL35A: U1.N19(PL35A)
SNN_CPRO_PL35B: U1.P18(PL35B)
SNN_CPRO_PL38A: U1.P19(PL38A)
SNN_CPRO_PL38B: U1.P20(PL38B)
SNN_CPRO_PL64B: U1.U25(PL64B)
SNN_CPRO_PL65A: U1.V18(PL65A)
SNN_CPRO_PL65B: U1.V19(PL65B)
SNN_CPRO_PL67A: U1.V20(PL67A)
SNN_CPRO_PL67B: U1.V21(PL67B)
SNN_CPRO_PR3B: U1.L1(PR3B)
SNN_CPRO_PR4A: U1.L2(PR4A/URC_GPLL0T_IN)
SNN_CPRO_PR4B: U1.L3(PR4B/URC_GPLL0C_IN)
SNN_CPRO_PR6A: U1.L6(PR6A)
SNN_CPRO_PR8A: U1.L8(PR8A)
SNN_CPRO_PR10A: U1.M9(PR10A)
SNN_CPRO_PR13B: U1.M4(PR13B/PMU_WAKEUPN)
SNN_CPRO_PR20A: U1.N4(PR20A)
SNN_CPRO_PR29A: U1.R6(PR29A/PCLKT1_1)
SNN_CPRO_PR31A: U1.R8(PR31A/PCLKT1_0)
SNN_CPRO_PR31B: U1.R9(PR31B)
SNN_CPRO_PR33A: U1.U8(PR33A)
SNN_CPRO_PR33B: U1.T8(PR33B)
SNN_CPRO_PR35A: U1.T7(PR35A)
SNN_CPRO_PR35B: U1.T6(PR35B)
SNN_CPRO_PR38A: U1.T5(PR38A)
SNN_CPRO_PR38B: U1.T4(PR38B)
SNN_CPRO_PR40A: U1.T3(PR40A)
SNN_CPRO_PR40B: U1.T2(PR40B)
SNN_CPRO_PR42A: U1.T1(PR42A/PCLKT2_0)
SNN_CPRO_PR42B: U1.U1(PR42B)
SNN_CPRO_PR44A: U1.U2(PR44A/PCLKT2_1)
SNN_CPRO_PR44B: U1.U3(PR44B)
SNN_CPRO_PR46A: U1.U6(PR46A/PCLKT2_2)
SNN_CPRO_PR46B: U1.U7(PR46B)
SNN_CPRO_PR47A: U1.V8(PR47A)
SNN_CPRO_PR47B: U1.V7(PR47B)
SNN_CPRO_PR49A: U1.V1(PR49A)
SNN_CPRO_PR49B: U1.V2(PR49B)
SNN_CPRO_PR51A: U1.V3(PR51A)
SNN_CPRO_PR51B: U1.V4(PR51B)
SNN_CPRO_PR53A: U1.V5(PR53A)
SNN_CPRO_PR53B: U1.V6(PR53B)
SNN_CPRO_PR55A: U1.W7(PR55A)
SNN_CPRO_PR55B: U1.W6(PR55B)
SNN_CPRO_PR56B: U1.W4(PR56B)
SNN_CPRO_PR64A: U1.AA2(PR64A)
SNN_CPRO_PR64B: U1.Y2(PR64B)
SNN_CPRO_PR65A: U1.AA1(PR65A)
SNN_CPRO_PR65B: U1.AB1(PR65B)
SNN_CPRO_PR67A: U1.AB3(PR67A)
SNN_CPRO_PR67B: U1.AB2(PR67B)
SNN_CPRO_PT142B: U1.H3(PT142B/MCSNO/MSDO)
SNN_CPRO_PT144A: U1.H2(PT144A)
SNN_CPRO_PT144B: U1.H1(PT144B)
SNN_CPRO_PT146A: U1.J1(PT146A)
SNN_CPRO_PT146B: U1.J2(PT146B)
SNN_CPRO_PT148A: U1.J3(PT148A)
SNN_CPRO_PT148B: U1.J5(PT148B)
SNN_CPRO_PT150A: U1.J6(PT150A)
SNN_CPRO_PT150B: U1.J7(PT150B)
SNN_CPRO_PT152A: U1.K8(PT152A)
SNN_CPRO_PT152B: U1.K7(PT152B)
SNN_CPRO_PT154A: U1.K6(PT154A)
SNN_CPRO_PT154B: U1.K4(PT154B)
SNN_CPRO_PT156A: U1.K3(PT156A)
SNN_CPRO_PT156B: U1.K2(PT156B)
SNN_ETH_REFCLK_NC: Y1.2(NC)
SNN_ETH_TXD2_N: U1.E26(SD0_TXDN)
SNN_ETH_TXD2_P: U1.F26(SD0_TXDP)
SNN_ETH_TXD3_N: U1.B26(SD1_TXDN)
SNN_ETH_TXD3_P: U1.C26(SD1_TXDP)
N20706841: R1.2 U2.6(CLK)

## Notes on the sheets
sheet 1
- CertusPro-NX Sensor to Ethernet Bridge Board
- Rev - A
- 01 - Title page
  02 - Block diagram
  03 - Power Tree
  04 - CertusPro-NX Bank 0,1
  05 - CertusPro-NX Bank 2,3,4,5
  06 - CertusPro-NX Bank 6,7,8
  07 - CertusPro-NX_SFP+, JESD
  08 - CertusPro-NX Power, GND
  09 - CrossLink_Bank0,1,3
  10 - CrossLink_Bank 4, 5, 6, 7
  11 -  CrossLink_Bank , Power, GND
  12 - Camera Connector Interface
  13 - FMC HPC
  14 - FMC Level Shifter and Coax
  15 - SFP+ Interface
  16 - Clock Synthesizer for Camera
- 17 - JTAG Chain
  18 - Volatge SW Regulator
  19 - USB Connector and LDOs
- OPN: LF-SNSR-ETH-EVN
sheet 2
- Block Diagram
sheet 3
- Power Tree
sheet 4
- CertusPro-Nx Config FLASH
- Bank-0
- 125MHz
- Bank-1
- I2C 7-bit address = 0x50
sheet 5
- Bank-2
- Bank-5
- Bank-4
- Bank-3
sheet 6
- Bank-6
- Bank-7
sheet 7
- JESD204B 4 LANE
- ETH_TXD are P/N swapped
  in FPGA pad to optomize
  PCB routing
- 10G ETH SFP 0
- 10G ETH SFP 1
- JESD204B 4 LANE
- JESD are P/N swapped in FPGA
  pad to optomize PCB routing
- SFP Reference Clock
sheet 8
- CertusPro-NX Core Power
- CertusPro-NX  NC Pin
- CertusPro-NX Ground
